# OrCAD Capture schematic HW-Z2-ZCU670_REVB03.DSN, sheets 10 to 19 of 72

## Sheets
10 010 Zynq Bank 503 - Config: size Custom
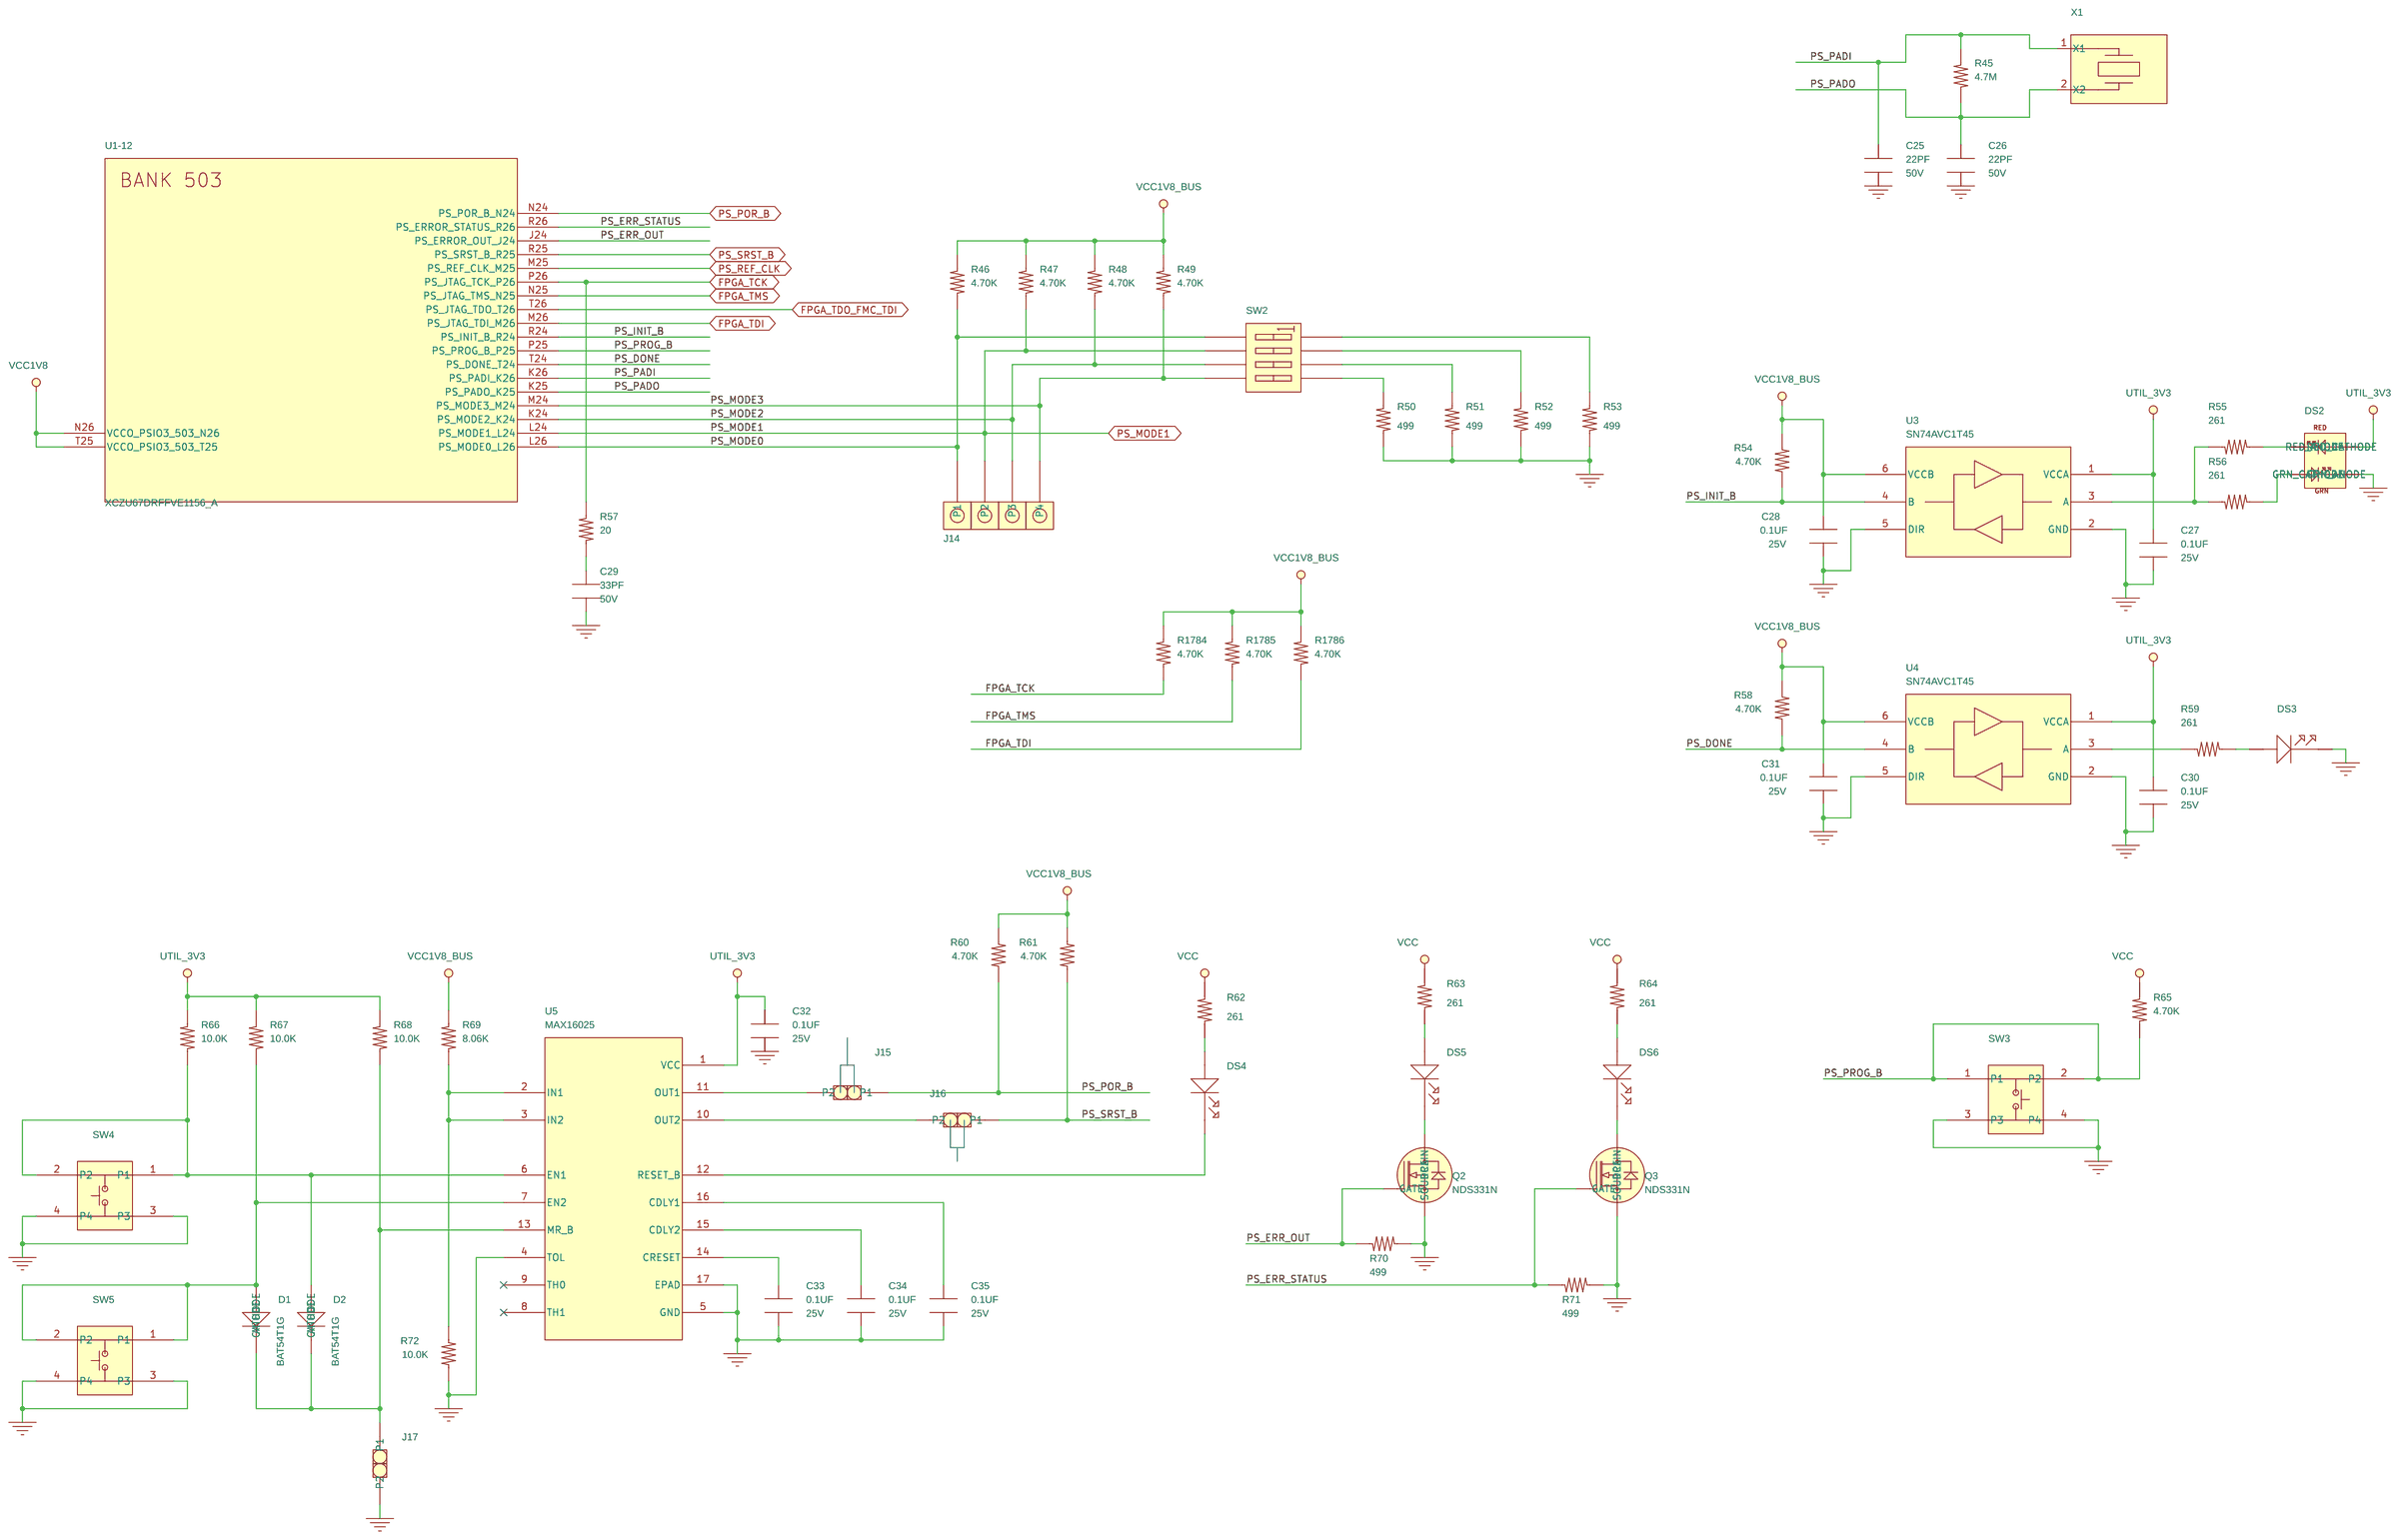
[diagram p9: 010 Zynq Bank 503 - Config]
11 011 Zynq Bank 504 - Memory: size Custom
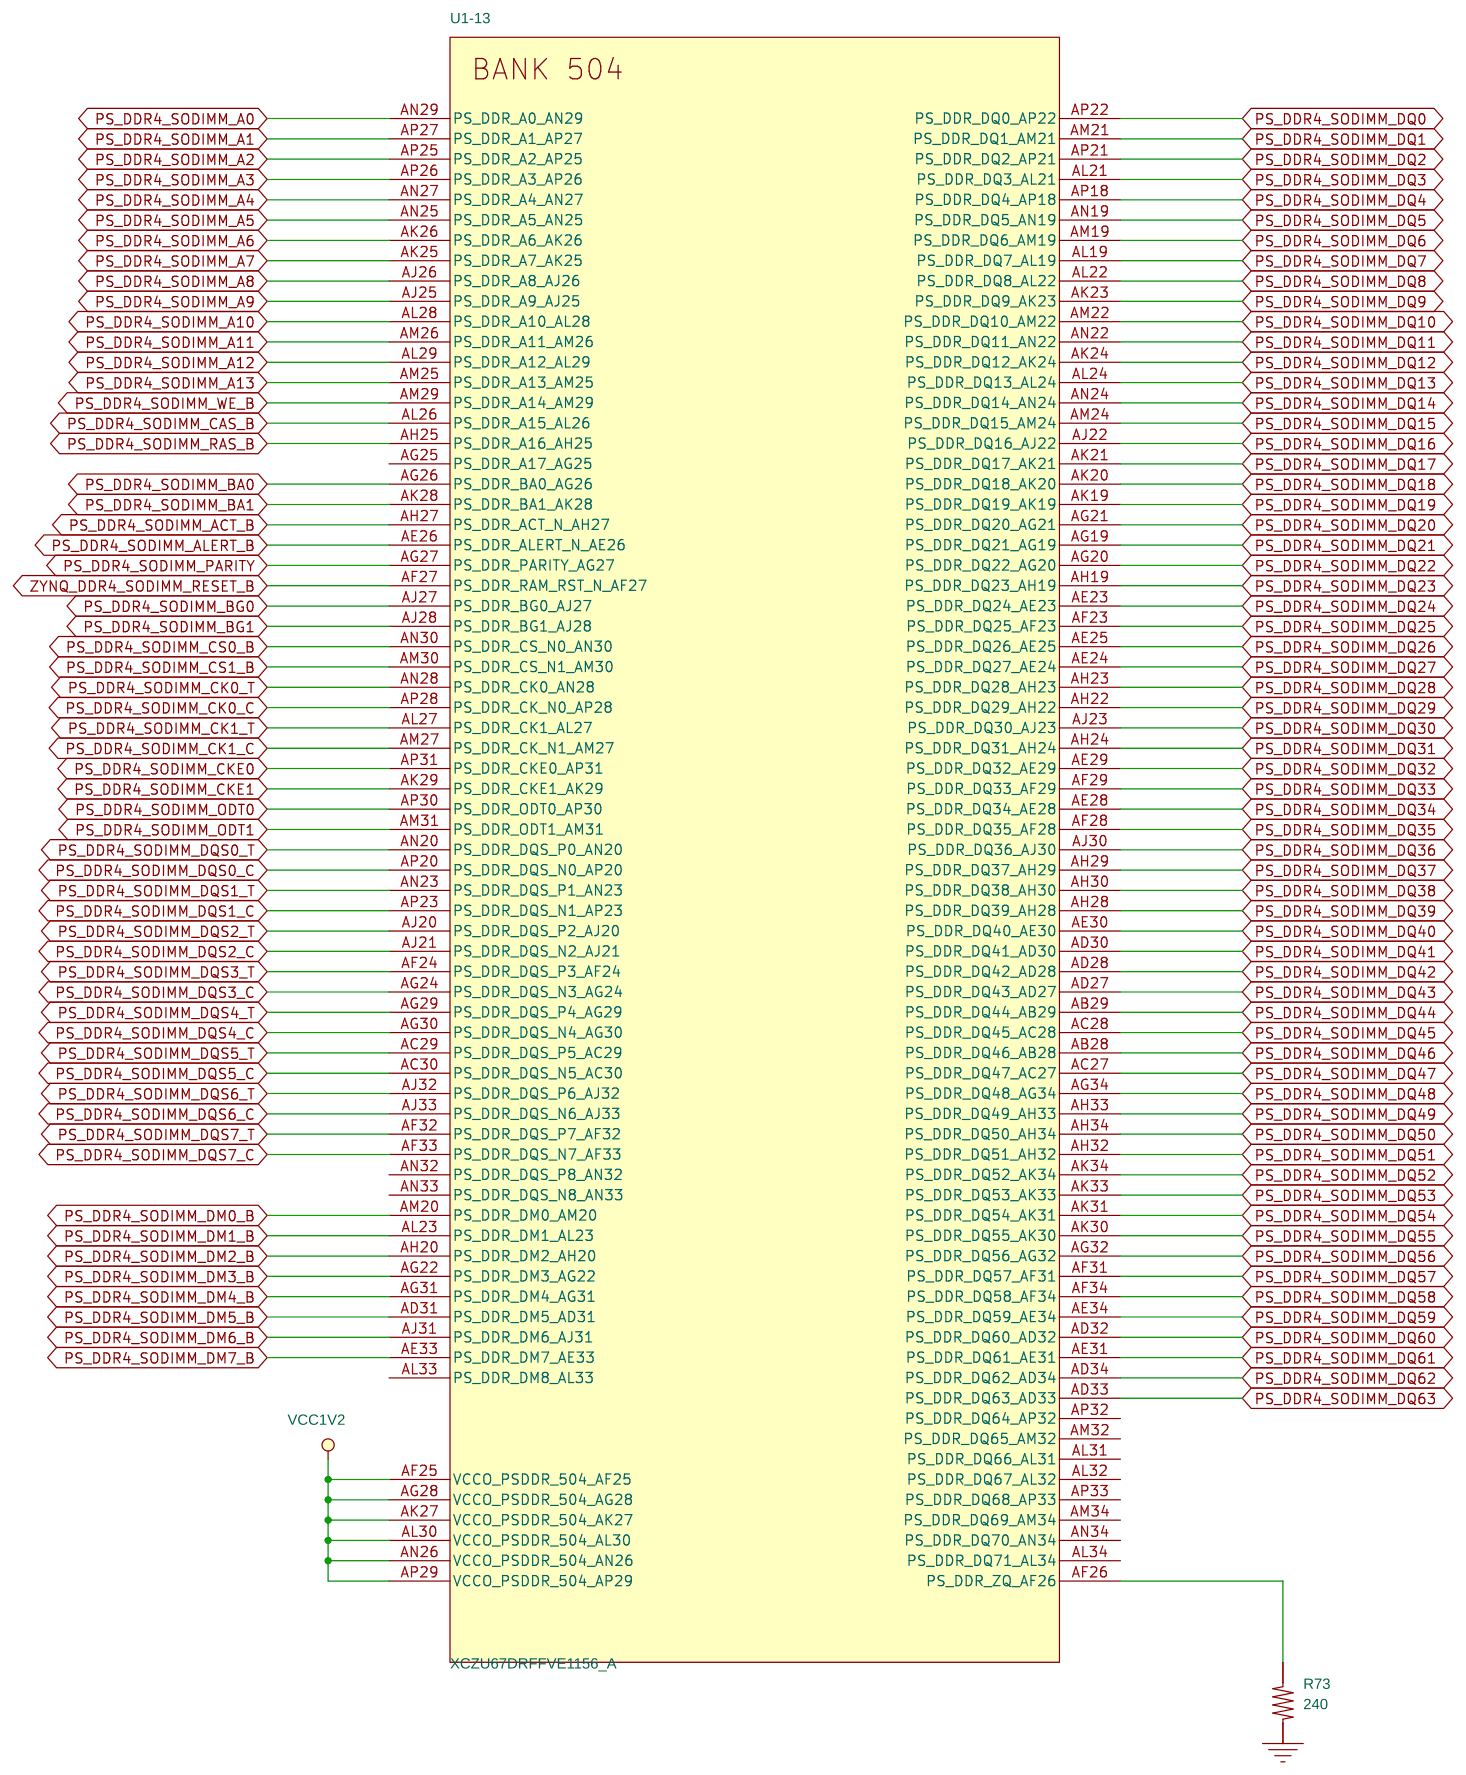
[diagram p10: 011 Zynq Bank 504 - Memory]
12 012 Zynq Bank 505 - GTR: size Custom
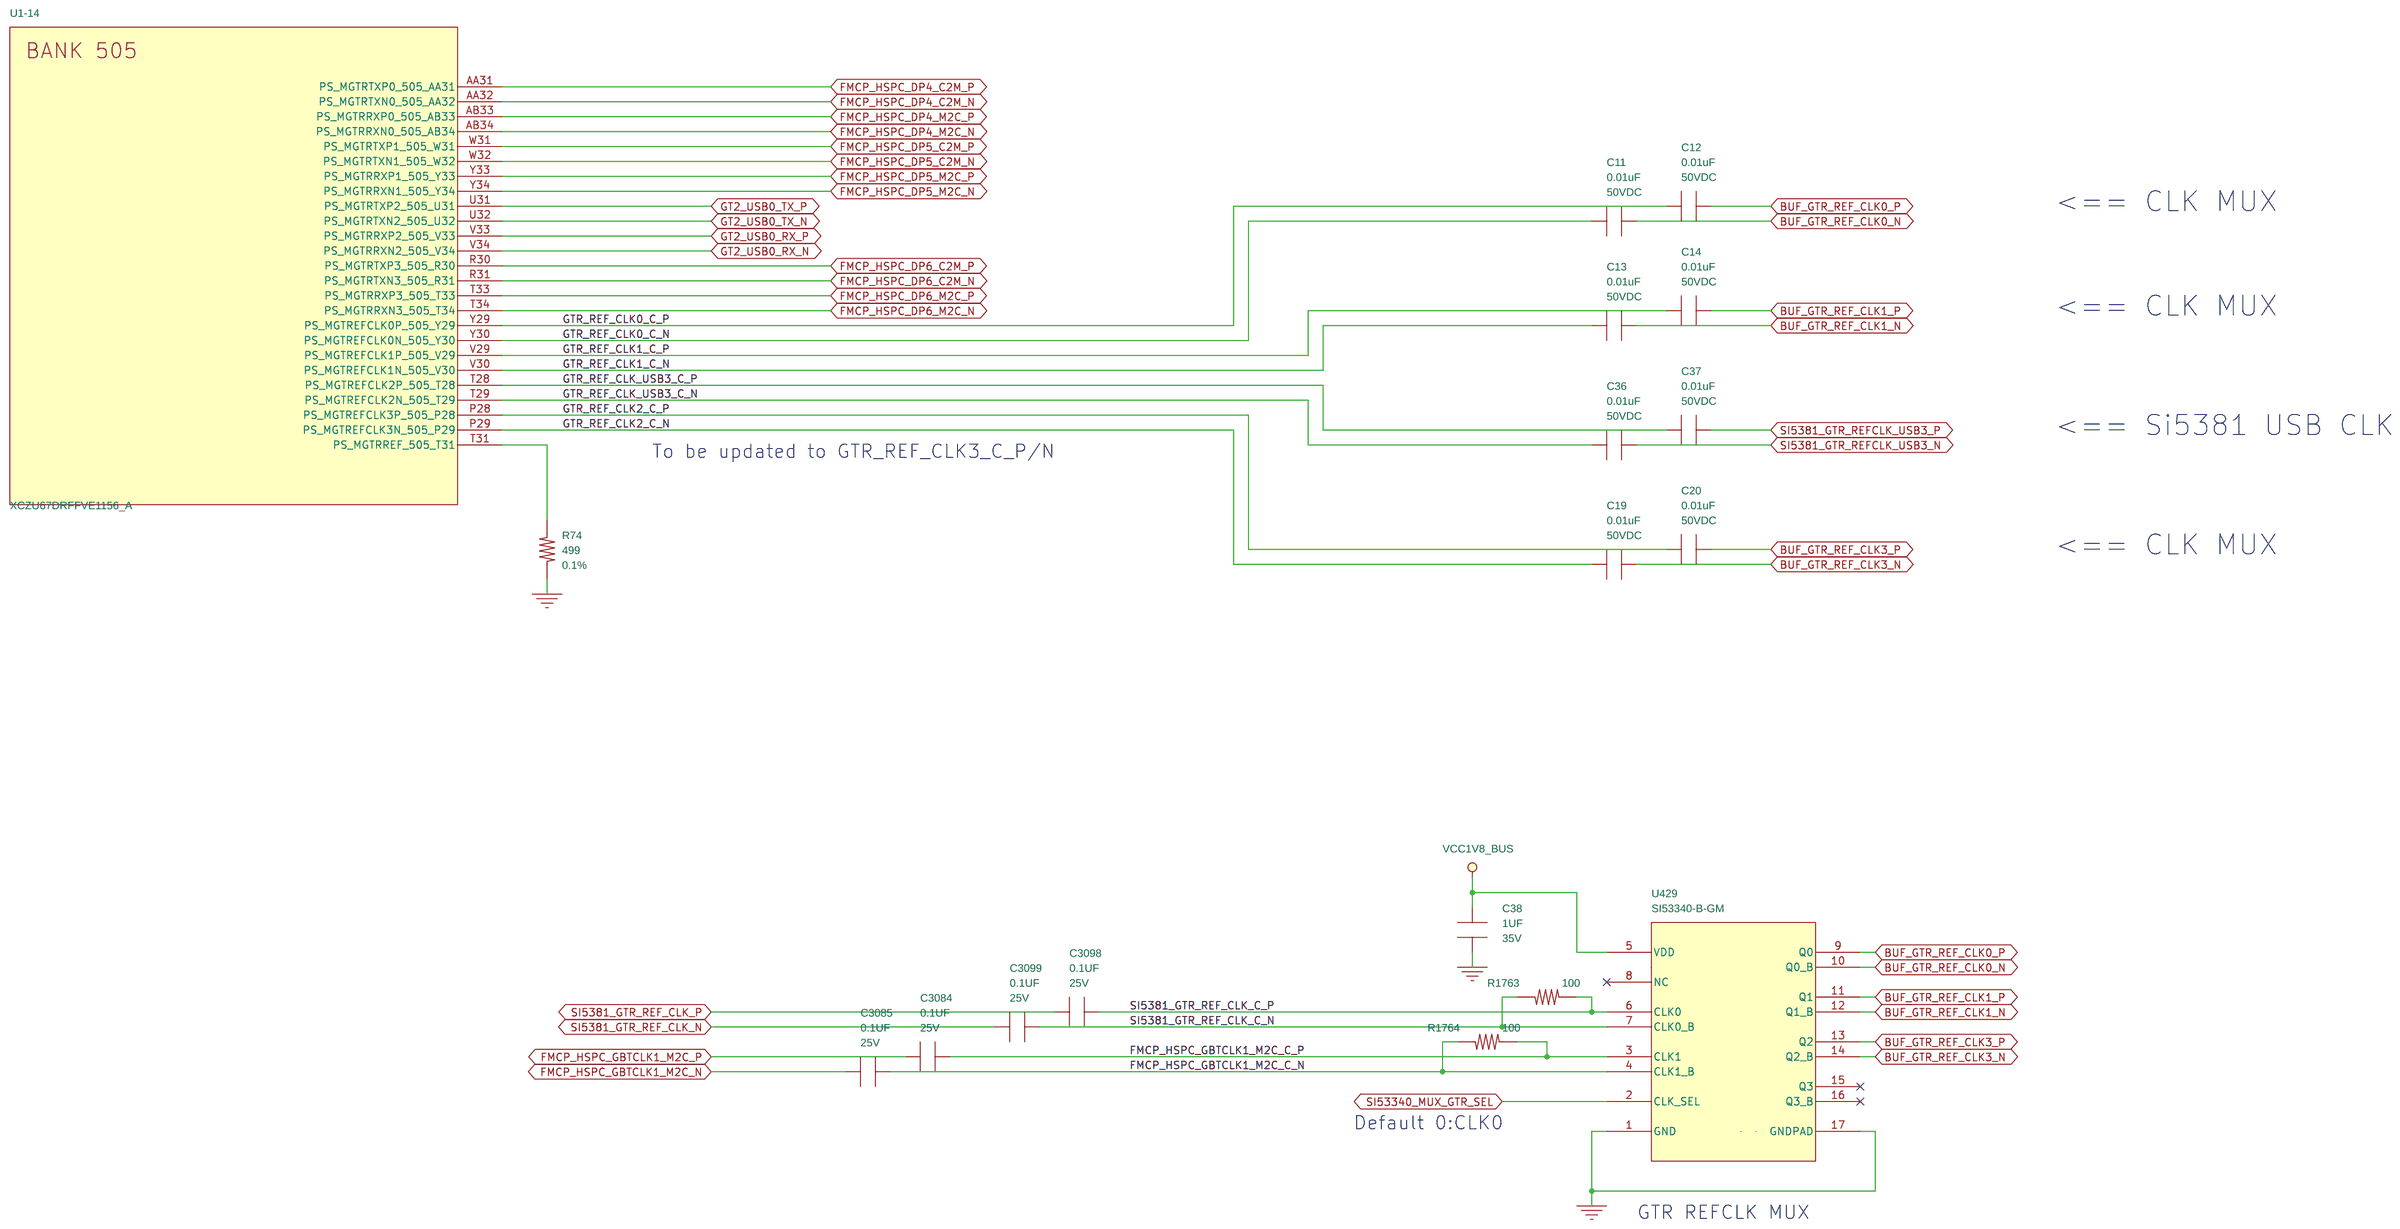
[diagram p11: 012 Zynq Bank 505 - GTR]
13 013 Zynq ADC Power: size Custom
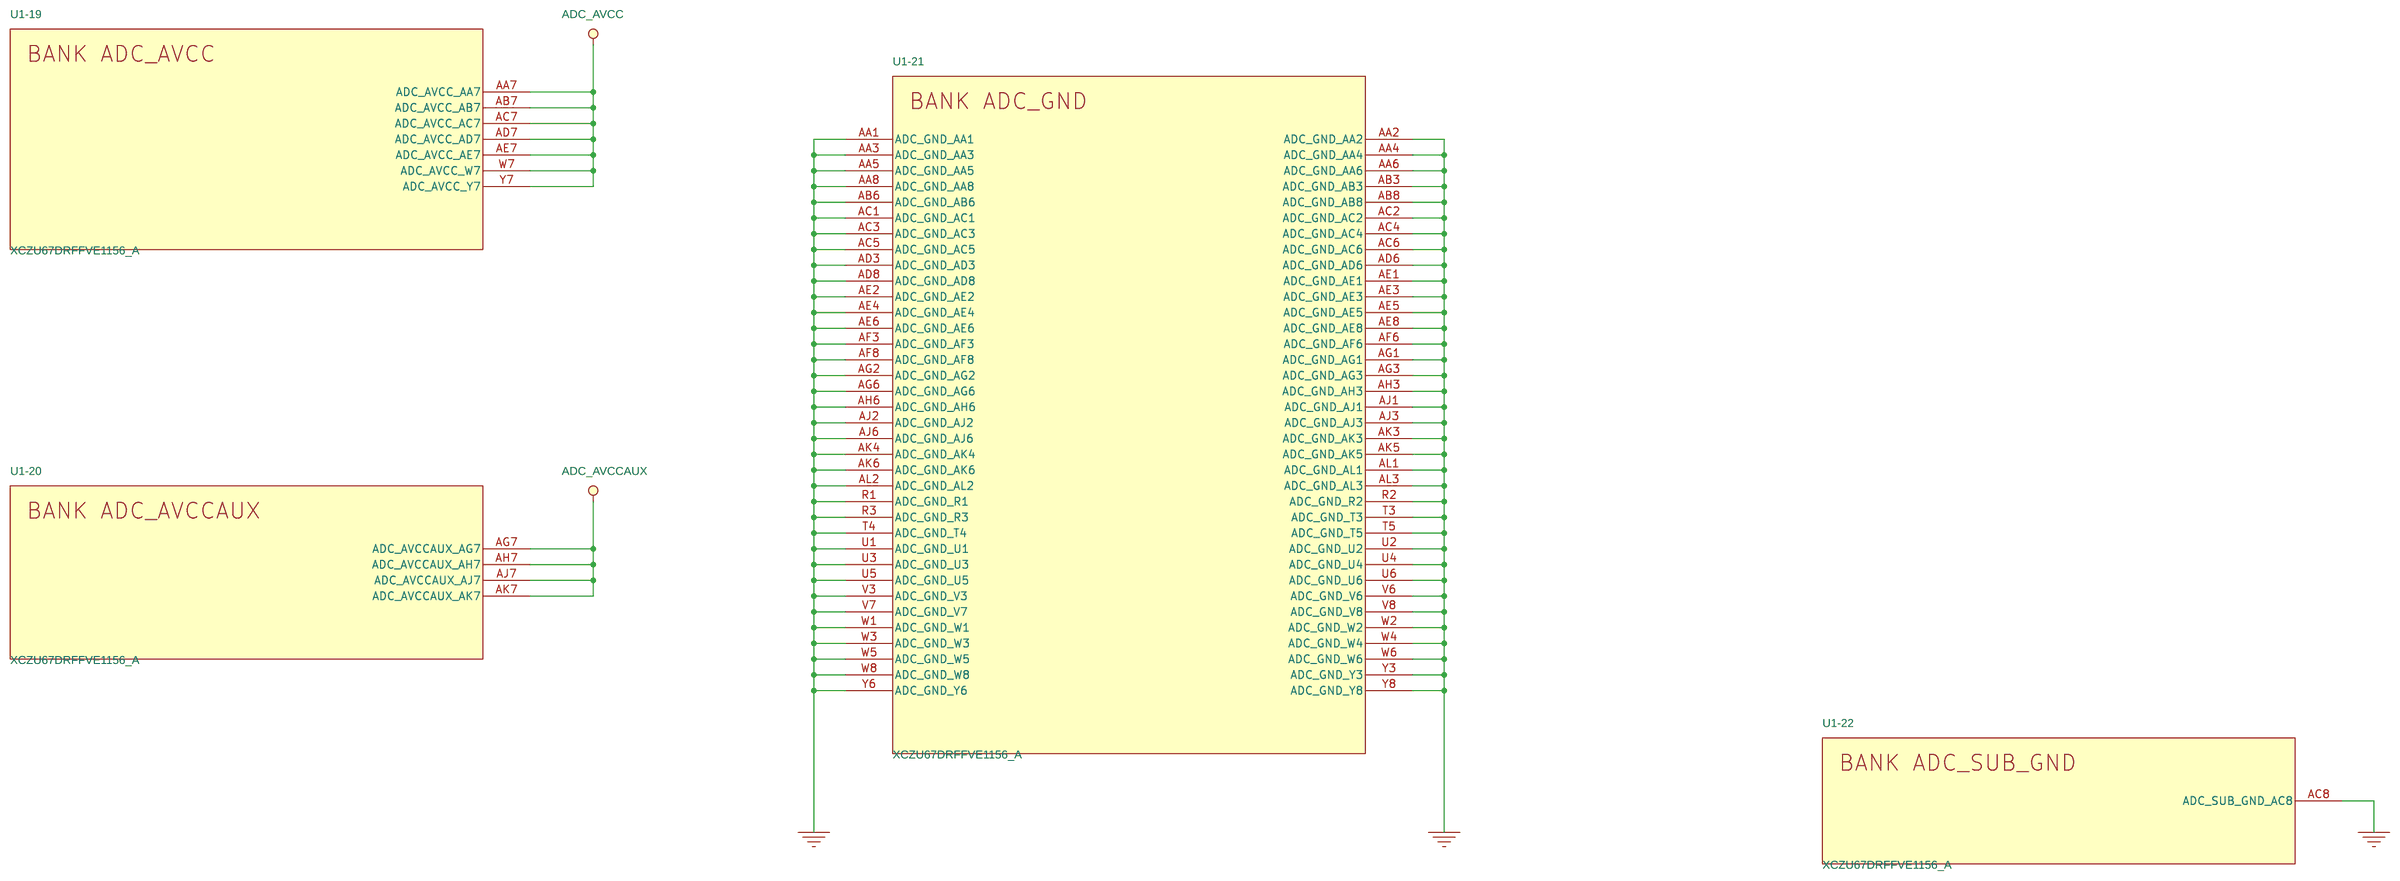
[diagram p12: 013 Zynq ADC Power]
14 014 Zynq DAC Power: size Custom
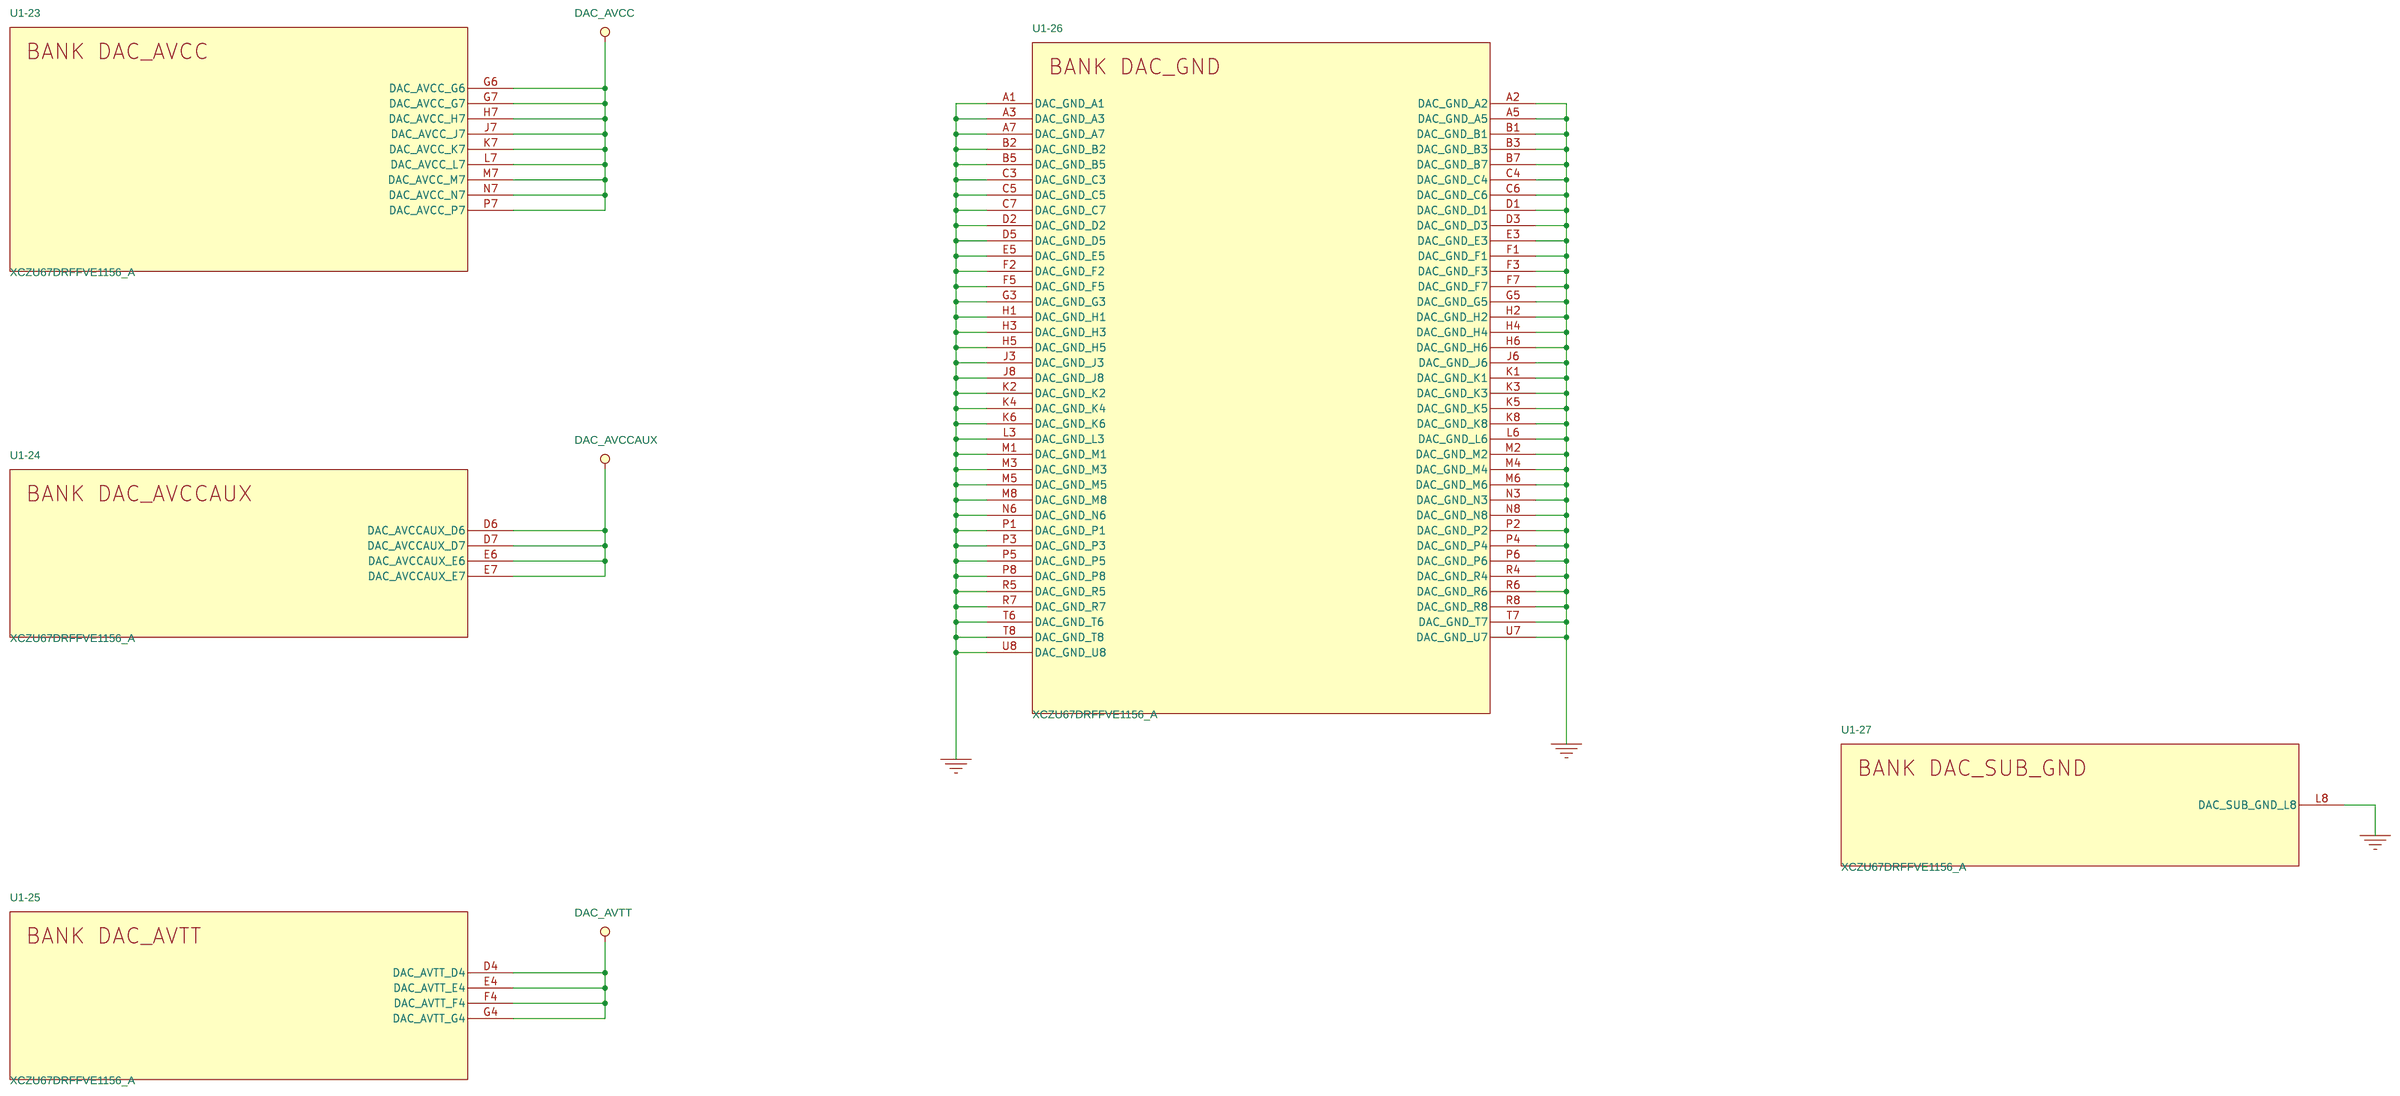
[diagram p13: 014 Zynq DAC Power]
15 015 Zynq Power 1: size Custom
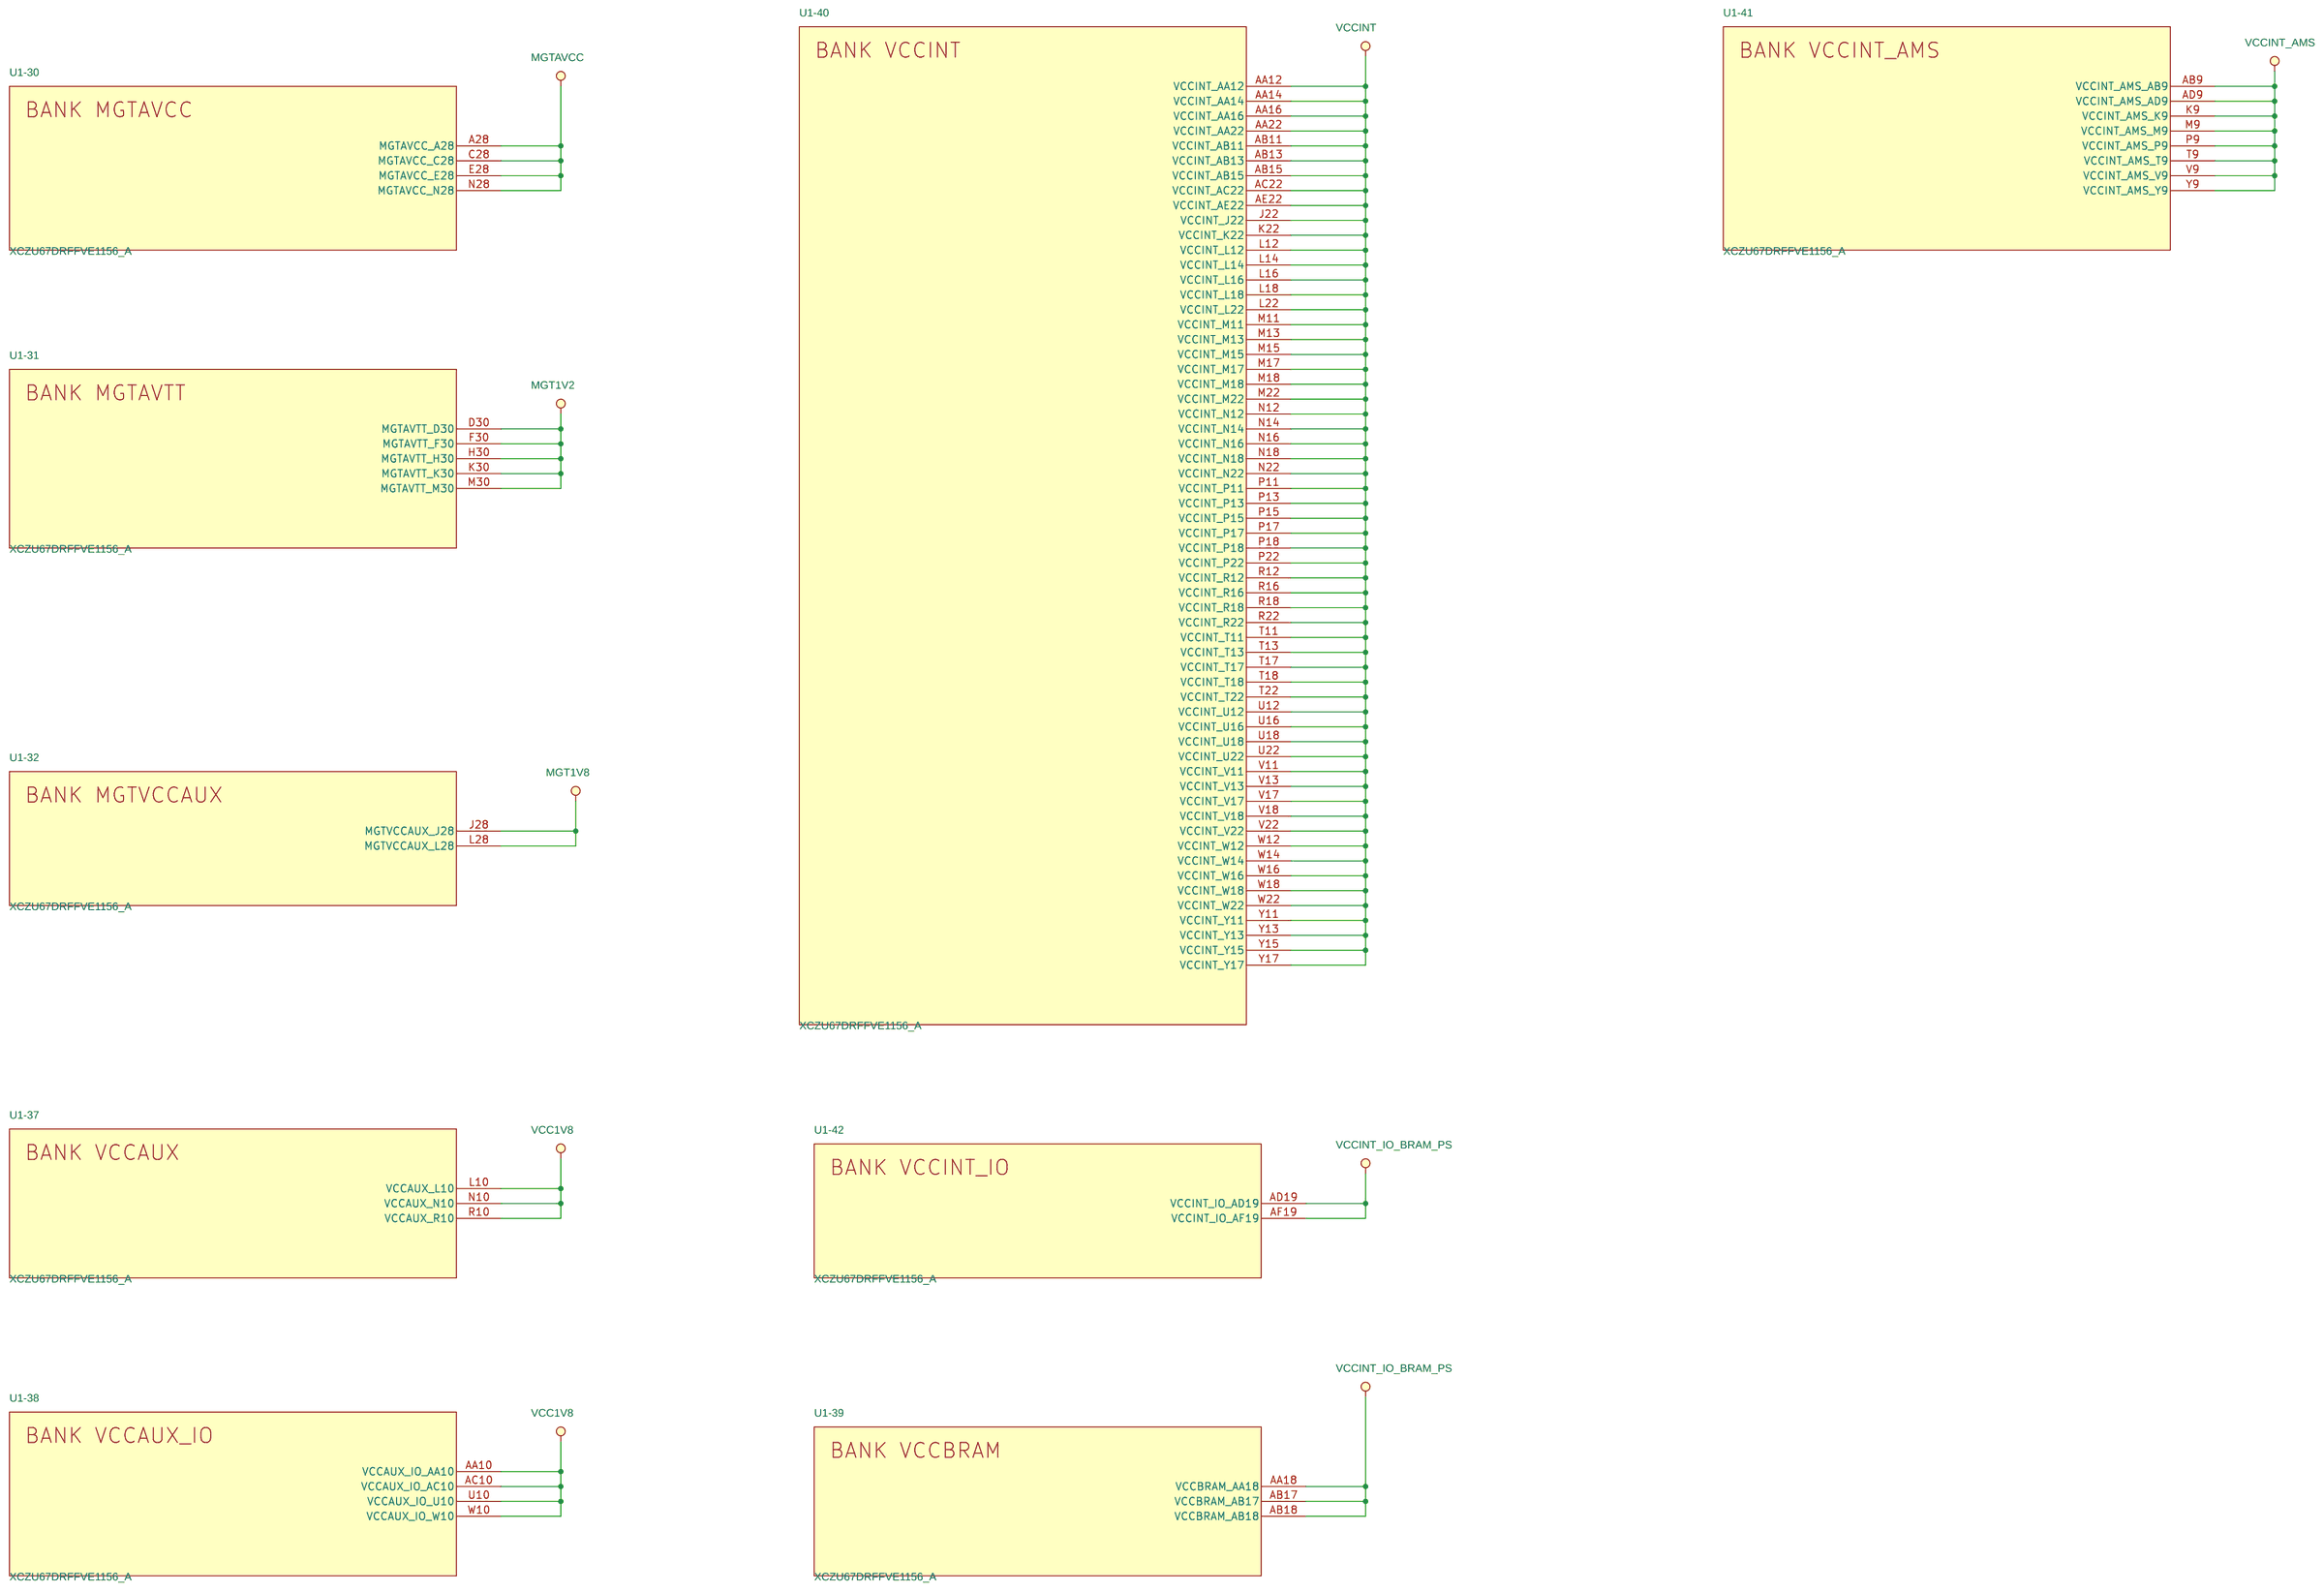
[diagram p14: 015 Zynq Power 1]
16 016 Zynq Power 2: size Custom
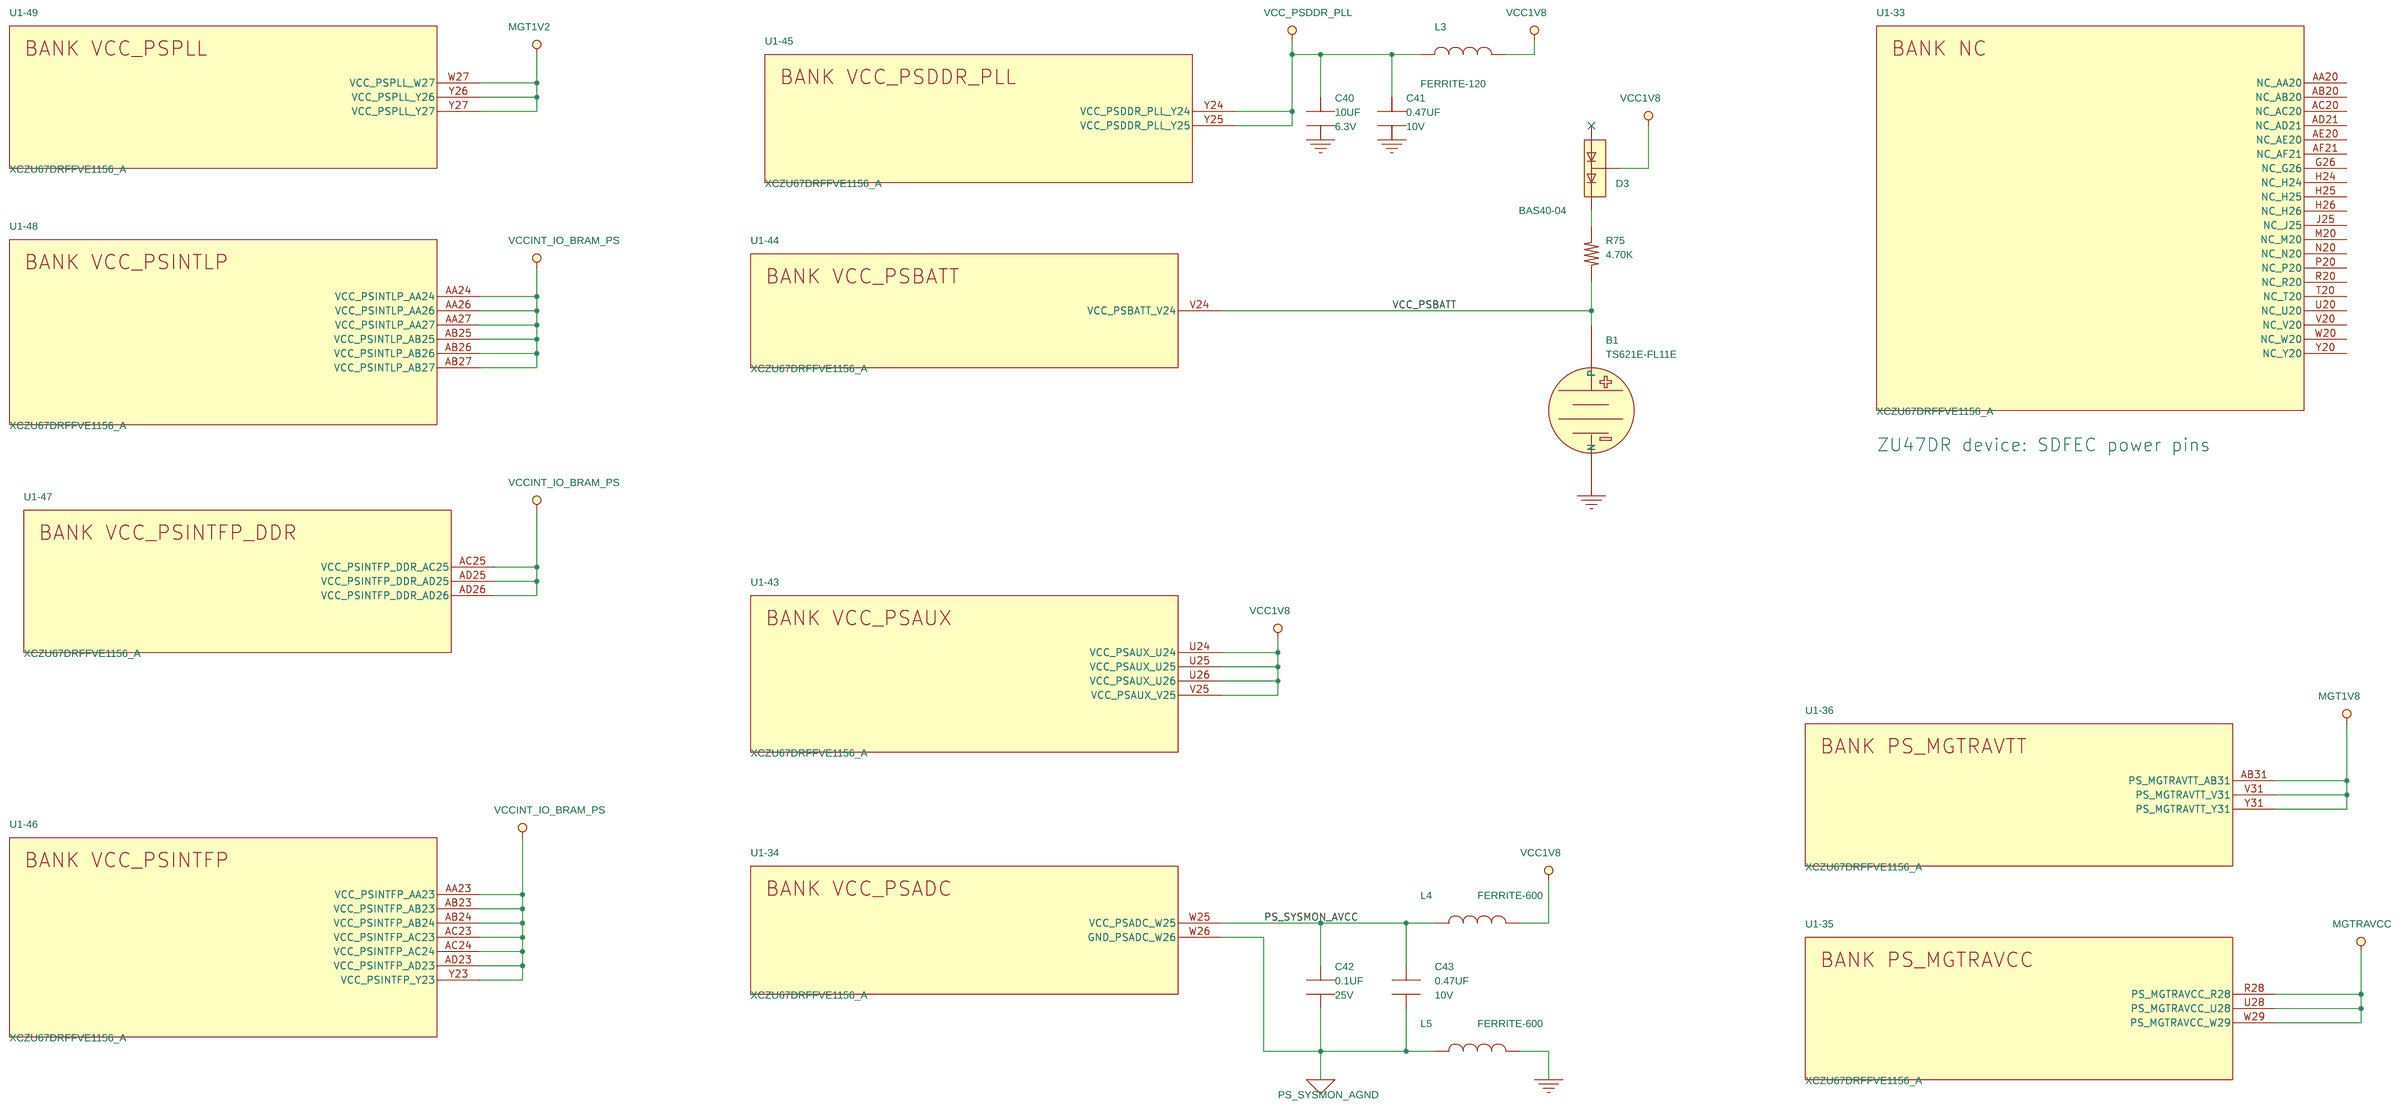
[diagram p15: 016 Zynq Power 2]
17 017 Zynq Decoupling: size Custom
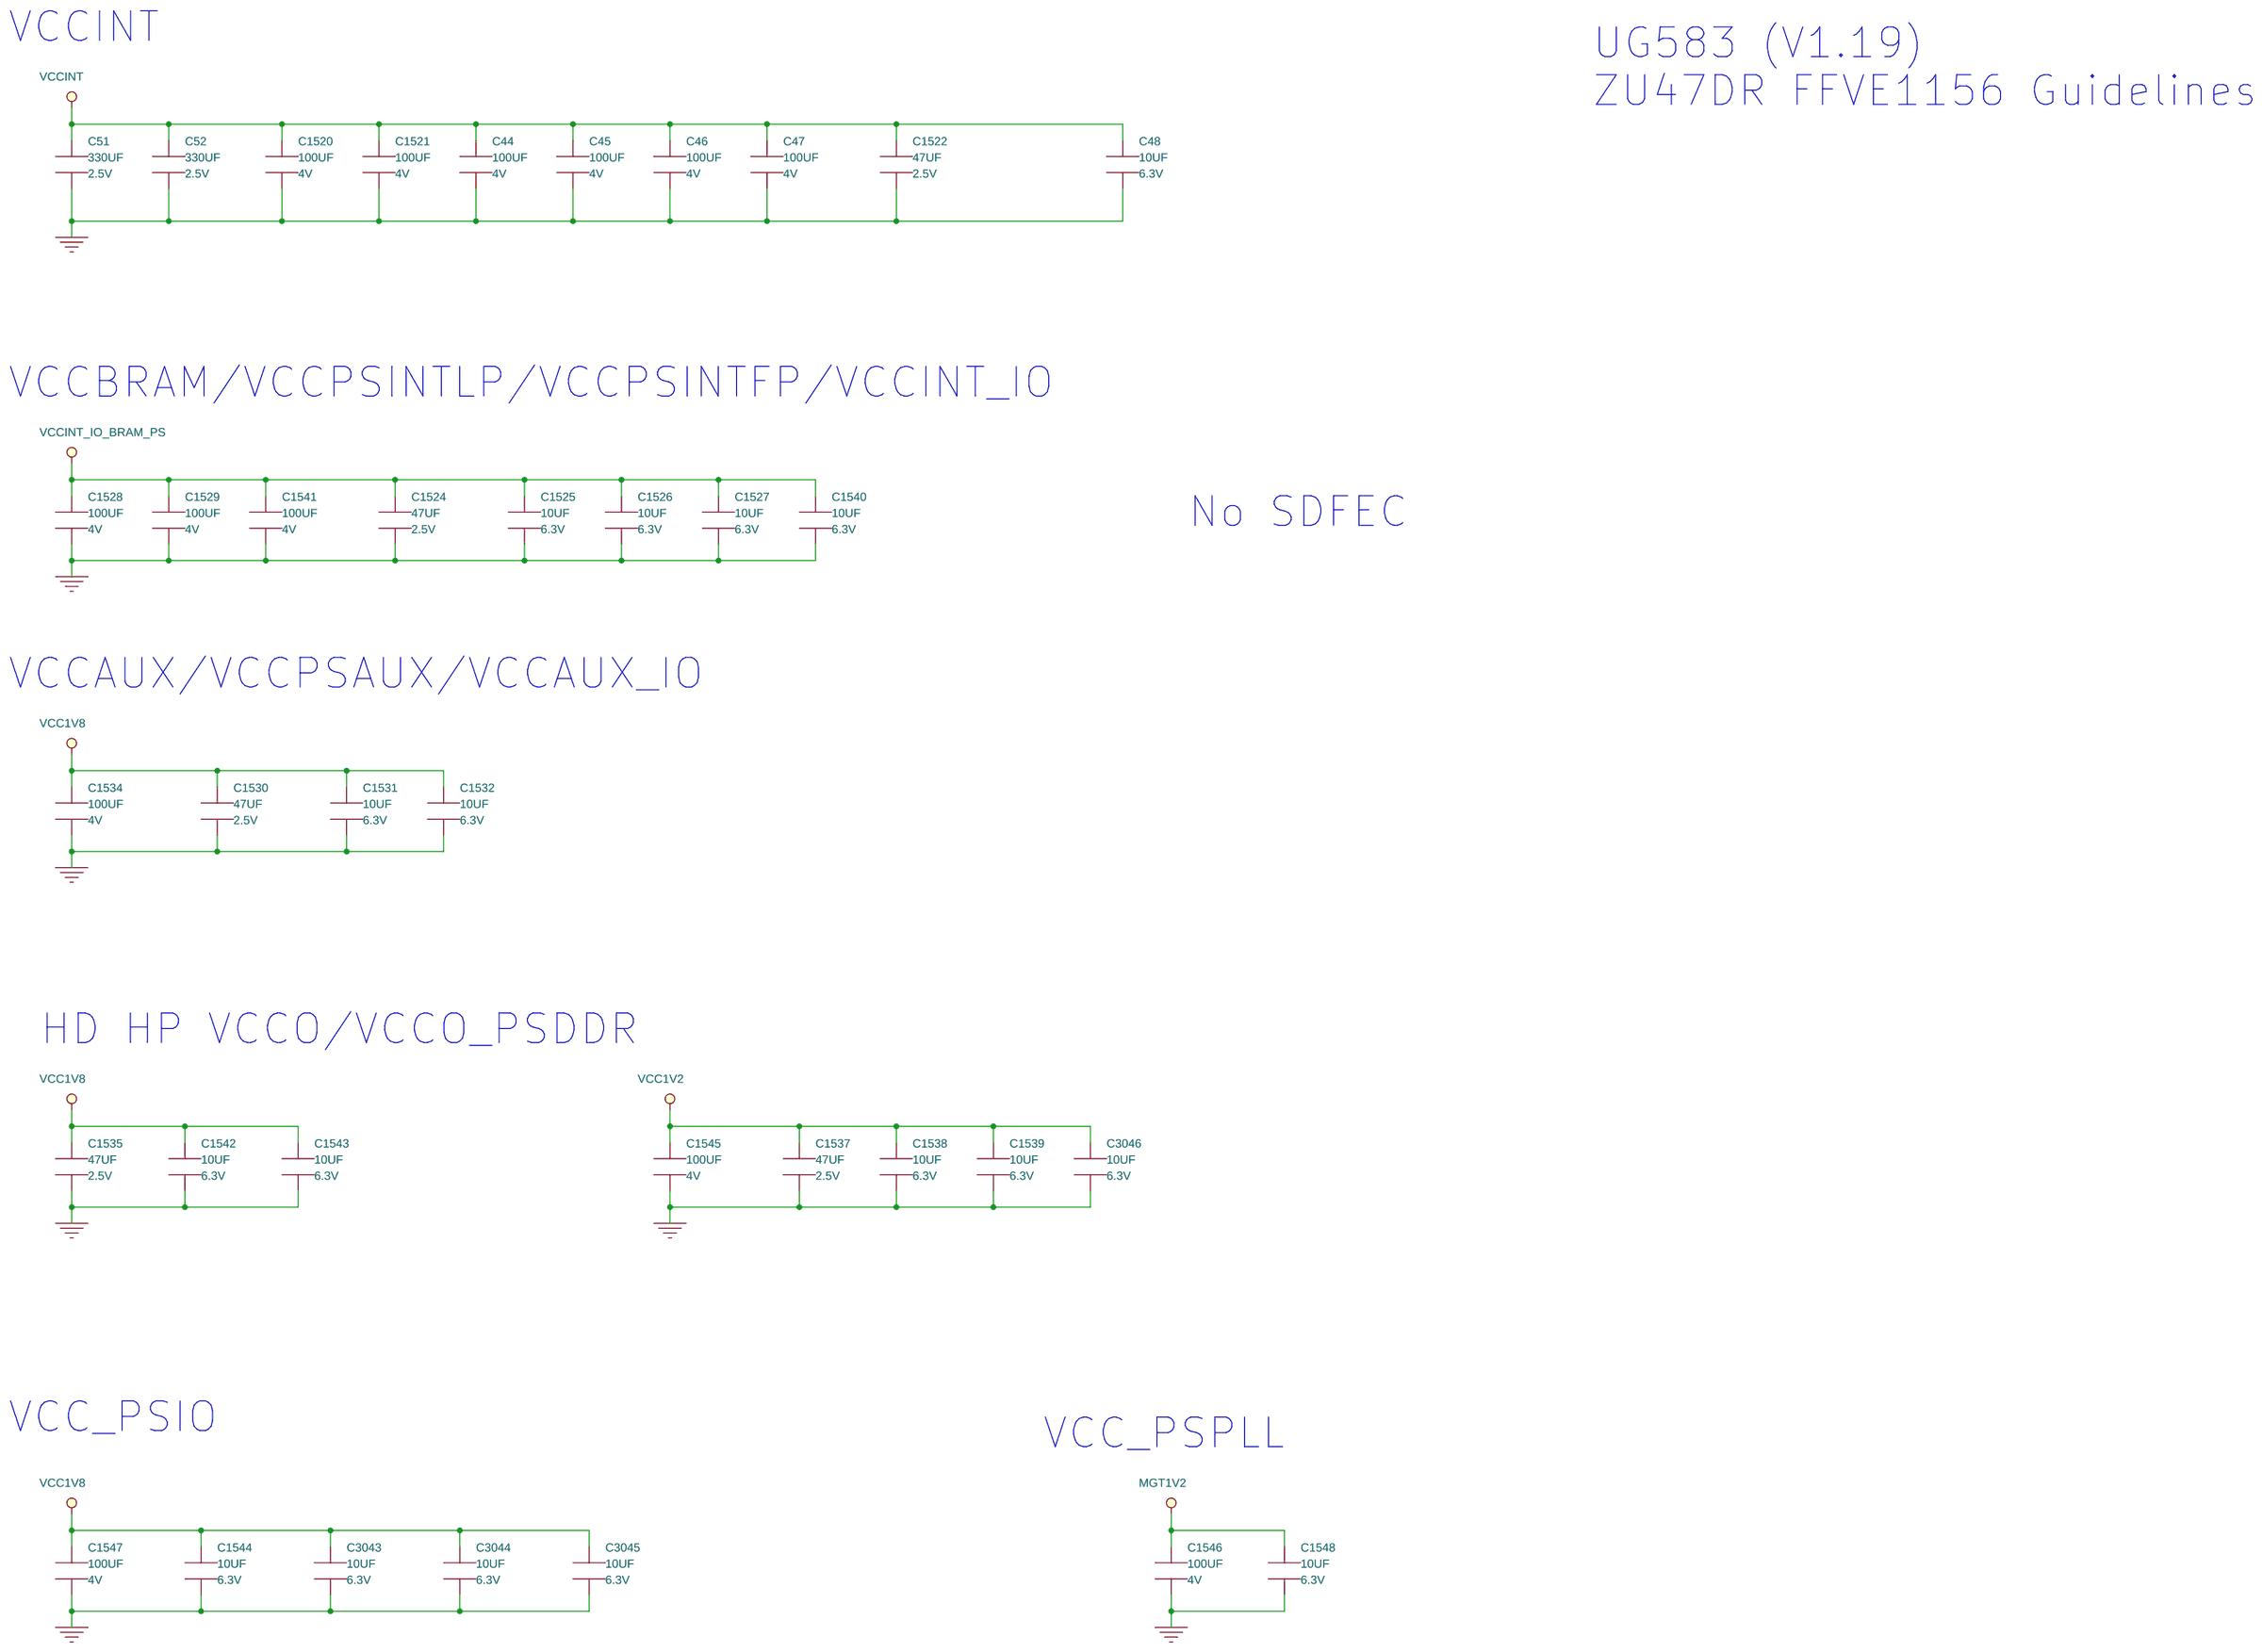
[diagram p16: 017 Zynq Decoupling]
18 018 Zynq Decoupling 2: size Custom
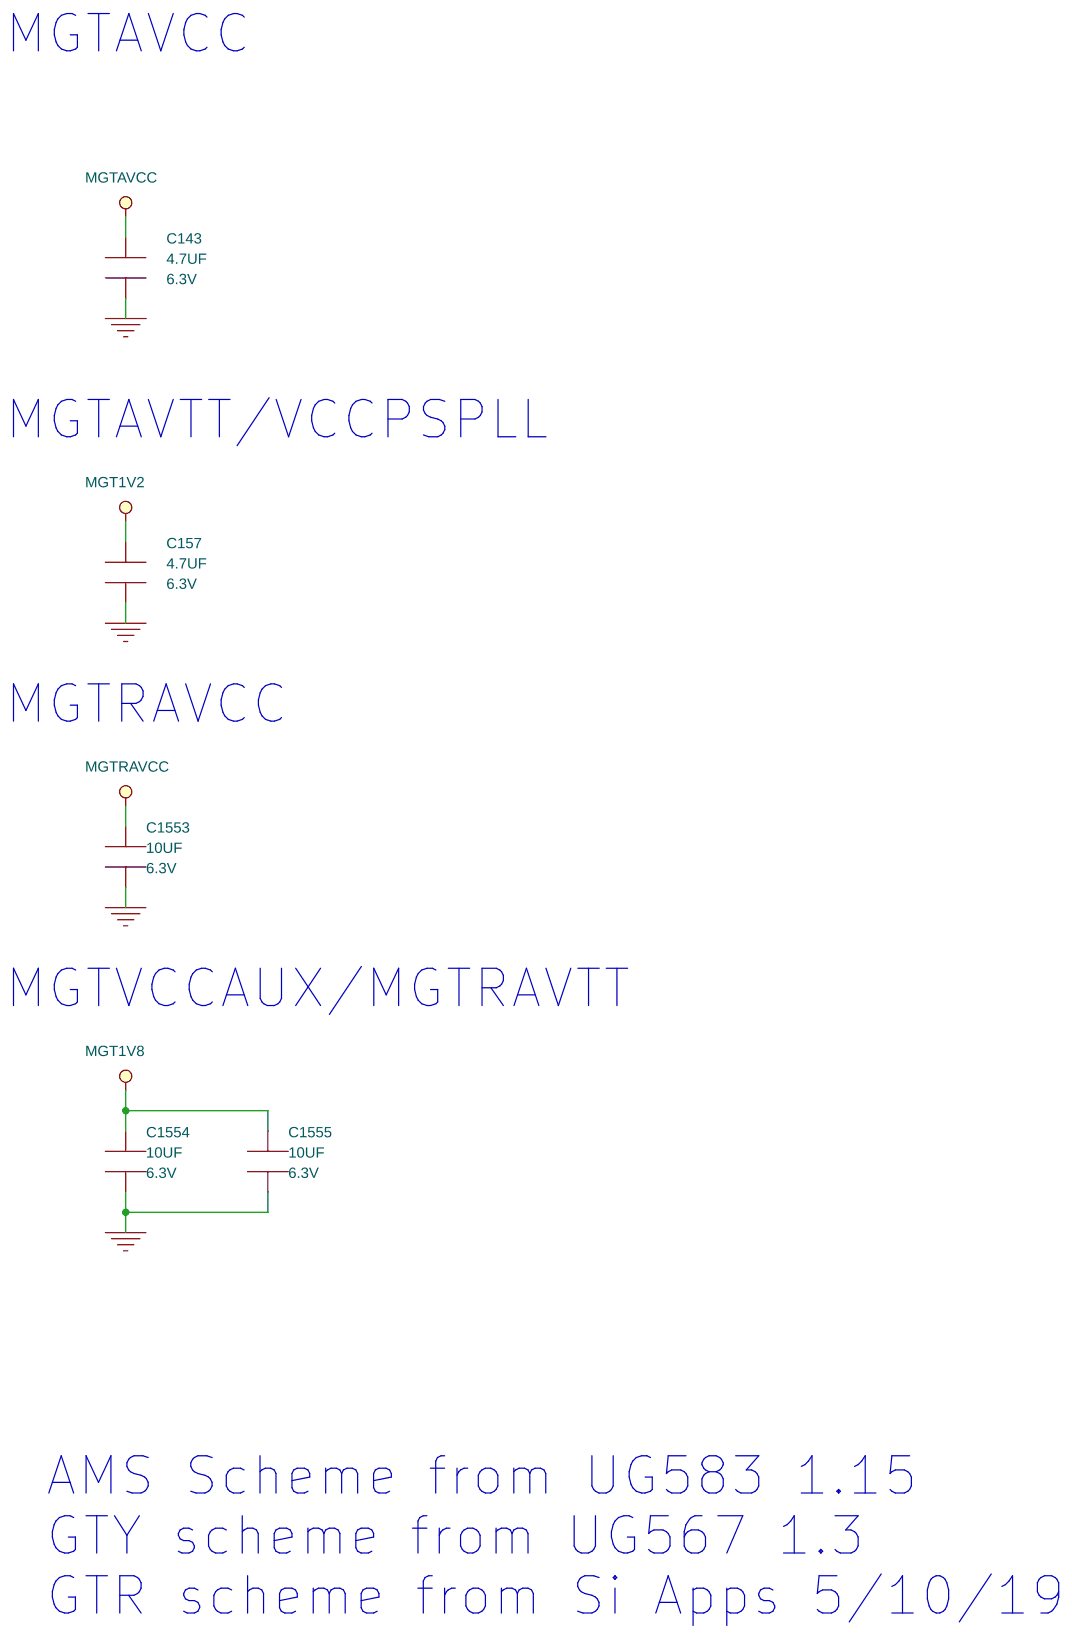
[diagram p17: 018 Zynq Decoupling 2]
19 019 Zynq GND: size Custom
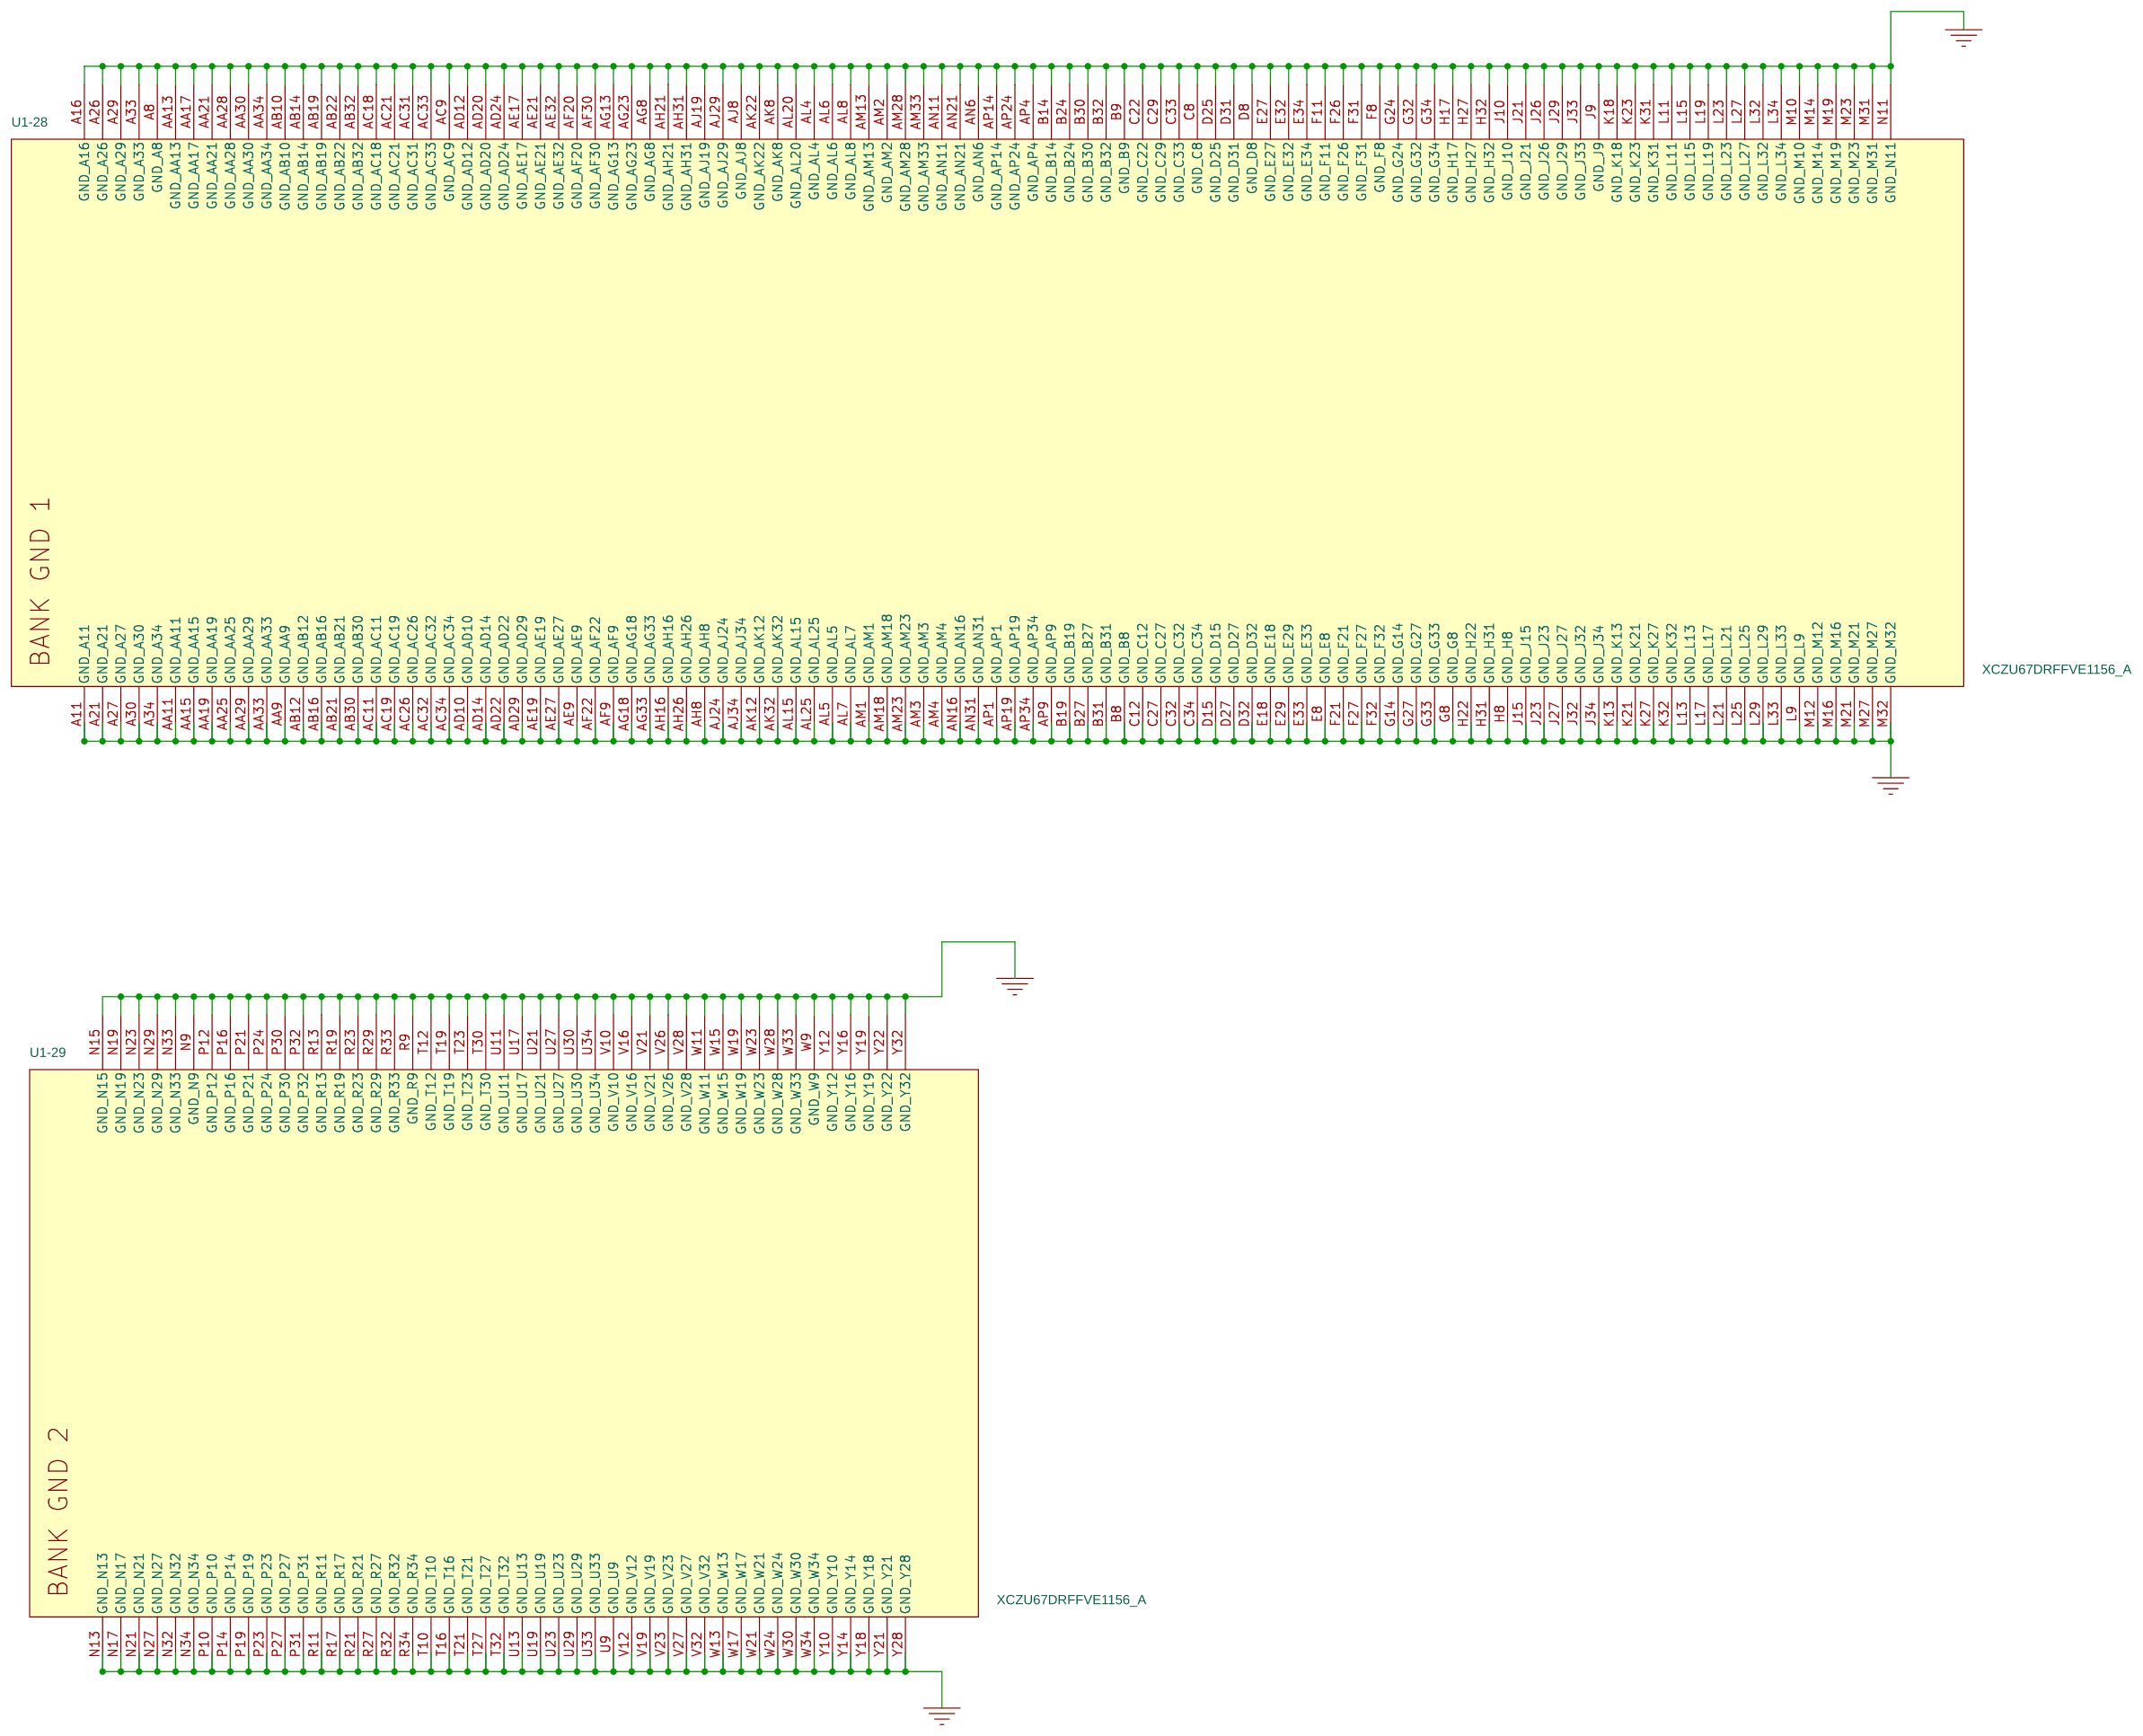
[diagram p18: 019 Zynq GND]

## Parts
sheet 010 Zynq Bank 503 - Config
C25  22PF  [CAPC100X50X56]
C26  22PF  [CAPC100X50X56]
C27  0.1UF  [CAPC100X50X55]
C28  0.1UF  [CAPC100X50X55]
C29  33PF  [CAPC100X50X56]
C30  0.1UF  [CAPC100X50X55]
C31  0.1UF  [CAPC100X50X55]
C32  0.1UF  [CAPC100X50X55]
C33  0.1UF  [CAPC100X50X55]
C34  0.1UF  [CAPC100X50X55]
C35  0.1UF  [CAPC100X50X55]
D1  BAT54T1G  [SOD_123]
D2  BAT54T1G  [SOD_123]
DS2  LED_GRN_RED  [HSMF_C15X]
DS3  LED-GRN-SMT  [LED_0603]
DS4  LED-RED-SMT  [LED_0603]
DS5  LED-RED-SMT  [LED_0603]
DS6  LED-RED-SMT  [LED_0603]
J14  HDR_1X4  [HDR_1X4]
J15  HDR_1X2  [HDR_1X2]
J16  HDR_1X2  [HDR_1X2]
J17  HDR_1X2  [HDR_1X2]
Q2  NDS331N  [SOT_23]
Q3  NDS331N  [SOT_23]
R45  4.7M  [RESC100X50X40]
R46  4.70K  [RESC100X50X40]
R47  4.70K  [RESC100X50X40]
R48  4.70K  [RESC100X50X40]
R49  4.70K  [RESC100X50X40]
R50  499  [RESC100X50X40]
R51  499  [RESC100X50X40]
R52  499  [RESC100X50X40]
R53  499  [RESC100X50X40]
R54  4.70K  [RESC100X50X40]
R55  261  [RESC100X50X40]
R56  261  [RESC100X50X40]
R57  20  [RESC100X50X40]
R58  4.70K  [RESC100X50X40]
R59  261  [RESC100X50X40]
R60  4.70K  [RESC100X50X40]
R61  4.70K  [RESC100X50X40]
R62  261  [RESC100X50X40]
R63  261  [RESC100X50X40]
R64  261  [RESC100X50X40]
R65  4.70K  [RESC100X50X40]
R66  10.0K  [RESC100X50X40]
R67  10.0K  [RESC100X50X40]
R68  10.0K  [RESC100X50X40]
R69  8.06K  [RESC100X50X40]
R70  499  [RESC100X50X40]
R71  499  [RESC100X50X40]
R72  10.0K  [RESC100X50X40]
R1784  4.70K  [RESC100X50X40]
R1785  4.70K  [RESC100X50X40]
R1786  4.70K  [RESC100X50X40]
SW2  SDA04H1SBD  [SW_SDA_8P]
SW3  TL3301EF100QG  [SW_TL3301_G_4P]
SW4  TL3301EF100QG  [SW_TL3301_G_4P]
SW5  TL3301EF100QG  [SW_TL3301_G_4P]
U3  SN74AVC1T45  [SC70_6]
U4  SN74AVC1T45  [SC70_6]
U5  MAX16025  [TQFN_16]
X1  32.768KHZ  [XTAL_TXC_9HT10]
sheet 011 Zynq Bank 504 - Memory
R73  240  [RESC100X50X40]
sheet 012 Zynq Bank 505 - GTR
C11  0.01uF  [CAPC100X50X55]
C12  0.01uF  [CAPC100X50X55]
C13  0.01uF  [CAPC100X50X55]
C14  0.01uF  [CAPC100X50X55]
C19  0.01uF  [CAPC100X50X55]
C20  0.01uF  [CAPC100X50X55]
C36  0.01uF  [CAPC100X50X55]
C37  0.01uF  [CAPC100X50X55]
C38  1UF  [CAPC100X50X60]
C3084  0.1UF  [CAPC60X30X40]
C3085  0.1UF  [CAPC60X30X40]
C3098  0.1UF  [CAPC60X30X40]
C3099  0.1UF  [CAPC60X30X40]
R74  499  [RESC100X50X40]
R1763  100  [RESC60X30X26]
R1764  100  [RESC60X30X26]
U429  SI53340-B-GM  [QFN16_SI_3X3MM]
sheet 016 Zynq Power 2
B1  TS621E-FL11E  [BAT_TS518_TS621_DUAL]
C40  10UF  [CAPC100X50X70]
C41  0.47UF  [CAPC100X50X55]
C42  0.1UF  [CAPC100X50X55]
C43  0.47UF  [CAPC100X50X55]
D3  BAS40-04  [SOT_23]
L3  FERRITE-120  [INDC160X80X65]
L4  FERRITE-600  [INDC200X125X110]
L5  FERRITE-600  [INDC200X125X110]
R75  4.70K  [RESC100X50X40]
U1  XCZU67DRFFVE1156_A  [SOC_1156_1MM_IRON_XILINX]  (sections -1,-10,-11,-12,-13,-14,-15,-16,-17,-18,-19,-2,-20,-21,-22,-23,-24,-25,-26,-27,-28,-29,-3,-30,-31,-32,-33,-34,-35,-36,-37,-38,-39,-4,-40,-41,-42,-43,-44,-45,-46,-47,-48,-49,-5,-6,-7,-8,-9)
sheet 017 Zynq Decoupling
C44  100UF  [CAPC200X125X145]
C45  100UF  [CAPC200X125X145]
C46  100UF  [CAPC200X125X145]
C47  100UF  [CAPC200X125X145]
C48  10UF  [CAPC100X50X70]
C51  330UF  [CAPC320X250X280]
C52  330UF  [CAPC320X250X280]
C1520  100UF  [CAPC200X125X145]
C1521  100UF  [CAPC200X125X145]
C1522  47UF  [CAPC160X80X80]
C1524  47UF  [CAPC160X80X80]
C1525  10UF  [CAPC100X50X70]
C1526  10UF  [CAPC100X50X70]
C1527  10UF  [CAPC100X50X70]
C1528  100UF  [CAPC200X125X145]
C1529  100UF  [CAPC200X125X145]
C1530  47UF  [CAPC160X80X80]
C1531  10UF  [CAPC100X50X70]
C1532  10UF  [CAPC100X50X70]
C1534  100UF  [CAPC200X125X145]
C1535  47UF  [CAPC160X80X80]
C1537  47UF  [CAPC160X80X80]
C1538  10UF  [CAPC100X50X70]
C1539  10UF  [CAPC100X50X70]
C1540  10UF  [CAPC100X50X70]
C1541  100UF  [CAPC200X125X145]
C1542  10UF  [CAPC100X50X70]
C1543  10UF  [CAPC100X50X70]
C1544  10UF  [CAPC100X50X70]
C1545  100UF  [CAPC200X125X145]
C1546  100UF  [CAPC200X125X145]
C1547  100UF  [CAPC200X125X145]
C1548  10UF  [CAPC100X50X70]
C3043  10UF  [CAPC100X50X70]
C3044  10UF  [CAPC100X50X70]
C3045  10UF  [CAPC100X50X70]
C3046  10UF  [CAPC100X50X70]
sheet 018 Zynq Decoupling 2
C143  4.7UF  [CAPC100X50X60]
C157  4.7UF  [CAPC100X50X60]
C1553  10UF  [CAPC100X50X70]
C1554  10UF  [CAPC100X50X70]
C1555  10UF  [CAPC100X50X70]

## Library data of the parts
C25 C26 = CAP_NP: Cap Cer 22pF 5% 50V C0G 0402; ALT_SYMBOLS: CAPC100X50X55RND; Agile Part Number: CAP-00003-01; CIP Link: http://xsjbrdwin1/CIP-E/Component/Index/All?pn=100099; Dielectric Type: C0G,NP0; OWNER: 3709; PRICE: 0; Part Type: CERAMIC; PartType: CERAMIC; ROHS: Yes; Tolerance: 5%; Voltage: 50V; barcode: 100099
C27 C28 C30-C35 C42 = CAP_NP: Cap Cer 100nF 10% 25V X5R 0402; ALT_SYMBOLS: CAPC100X50X55RND; Agile Part Number: CAP-00068-01; CIP Link: http://xsjbrdwin1/CIP-E/Component/Index/All?pn=100040; Dielectric Type: X5R; OWNER: 4001; PRICE: 0.01; Part Type: CERAMIC; PartType: CERAMIC; ROHS: Yes; Tolerance: 10%; Voltage: 25V; barcode: 100040
C29 = CAP_NP: Cap Cer 33pF 5% 50V C0G 0402; ALT_SYMBOLS: CAPC100X50X56RND; Agile Part Number: CAP-00013-01; CIP Link: http://xsjbrdwin1/CIP-E/Component/Index/All?pn=100188; Dielectric Type: NP0; OWNER: 3670; PRICE: 0; Part Type: CERAMIC; PartType: CERAMIC; ROHS: Yes; Tolerance: 5%; Voltage: 50V; barcode: 100188
D1 D2 = BAT54T1G: Diode Schottky 200mA 30V SOD-123; Agile Part Number: DIO-00008-01; Barcode: 300002; CIP Link: http://xsjbrdwin1/CIP-E/Component/Index/All?pn=300002; OWNER: 3501; PRICE: 0.08; Part Type: SWITCHING; PartType: SWITCHING; Power: 400MW; ROHS: 1; Rated Power: 400MW; Voltage: 30V
DS2 = HSMF_C155: LED Bi-Color Clear Green/Red 20mA 5V 570/635nm Dom 3.2x2.7mm SMT; Agile Part Number: DIO-00103-01; Barcode: 70000027; CIP Link: http://xsjbrdwin1/CIP-E/Component/Index/All?pn=70000027; Part Type: LED DUAL
DS3 = LED: LED Green Diffused 20mA 5V 570nm 0603; Agile Part Number: DIO-00003-01; Barcode: 300021; CIP Link: http://xsjbrdwin1/CIP-E/Component/Index/All?pn=300021; OWNER: 4001; PRICE: 0.1; Power: 2.2-20MA; ROHS: Yes; Rated Power: 2.2-20MA; Voltage: 2.2V
DS4-DS6 = LED: LED Red Diffused 20mA 5V 630nm 0603; Agile Part Number: DIO-00005-01; Barcode: 300022; CIP Link: http://xsjbrdwin1/CIP-E/Component/Index/All?pn=300022; OWNER: 4001; PRICE: 0.08; Power: 2.0-20MA; ROHS: Yes; Rated Power: 2.0-20MA; Voltage: 2.0V
J14 = HDR_1X4: Conn Hdr Vert 4  Pos 1x4 2.54mm P Black TH; Agile Part Number: CON-00039-01; Barcode: 390104; CIP Link: http://xsjbrdwin1/CIP-E/Component/Index/All?pn=390104; Part Type: HEADER; Pins: 4PINS; Pitch: 0.100; ROHS: Yes
J15-J17 = HDR_1X2: Conn Hdr Male Vert 2 Pos 1x2 2.54mm P Black TH; Agile Part Number: CON-00037-01; Barcode: 390102; CIP Link: http://xsjbrdwin1/CIP-E/Component/Index/All?pn=390102; OWNER: 4001; PRICE: 0.03; Part Type: HEADER; PartType: HEADER; Pins: 2PINS; Pitch: 0.100; ROHS: Yes
Q2 Q3 = FET-3PIN: MOSFET N-Ch 20V 1.3A 160mR SSOT-3; Agile Part Number: TRN-00012-01; Barcode: 500100; CIP Link: http://xsjbrdwin1/CIP-E/Component/Index/All?pn=500100; OWNER: 4001; PRICE: 0.12; Part Type: FET; PartType: FET; Power: 460MW; ROHS: Yes; Rated Power: 460MW; Rated Voltage: 20V
R45 = RES: Res 4M7 5% 1/16W -400/150PPM 50V 0402; ALT_SYMBOLS: RESC100X50X40RND; Agile Part Number: RES-00323-01; Barcode: 200358; CIP Link: http://xsjbrdwin1/CIP-E/Component/Index/All?pn=200358; OWNER: 10460; PRICE: 0; Part Type: SMT - 5%; PartType: SMT - 5%; Power: 1/10W; ROHS: Yes; Rated Power: 1/16W; Tolerance: 5%; primarykey: 207
R46-R49 R54 R58 R60 R61 R65 R75 R1784-R1786 = RES: Res 4K7 1% 1/16W 100PPM 50V 0402; ALT_SYMBOLS: RESC100X50X40RND; Agile Part Number: RES-00035-01; Barcode: 200067; CIP Link: http://xsjbrdwin1/CIP-E/Component/Index/All?pn=200067; OWNER: 3670; PRICE: 0.01; Part Type: SMT - 1%; PartType: SMT - 1%; Power: 1/16W; ROHS: Yes; Rated Power: 1/16W; Tolerance: 1%; primarykey: 128
R50-R53 R70 R71 = RES: Res 499R 1% 1/16W 100PPM 50V 0402; ALT_SYMBOLS: RESC100X50X40RND; Agile Part Number: RES-00028-01; Barcode: 200071; CIP Link: http://xsjbrdwin1/CIP-E/Component/Index/All?pn=200071; OWNER: 10460; PRICE: 0; Part Type: SMT - 1%; PartType: SMT - 1%; Power: 1/10W; ROHS: Yes; Rated Power: 1/16W; Tolerance: 1%; primarykey: 79
R55 R56 R59 R62-R64 = RES: Res 261R 1% 1/16W 100PPM 50V 0402; ALT_SYMBOLS: RESC100X50X40RND; Agile Part Number: RES-00086-01; Barcode: 200050; CIP Link: http://xsjbrdwin1/CIP-E/Component/Index/All?pn=200050; OWNER: 3501; PRICE: 0; Part Type: SMT - 1%; PartType: SMT - 1%; Power: 1/10W; ROHS: Yes; Rated Power: 1/16W; Tolerance: 1%; primarykey: 60
R57 = RES: Res 20R 1% 1/16W 100PPM 50V 0402; ALT_SYMBOLS: RESC100X50X40RND; Agile Part Number: RES-00033-01; Barcode: 200119; CIP Link: http://xsjbrdwin1/CIP-E/Component/Index/All?pn=200119; OWNER: 4001; PRICE: 0; Part Type: SMT - 1%; PartType: SMT - 1%; Power: 1/16W; ROHS: Yes; Rated Power: 1/16W; Tolerance: 1%; primarykey: 78
R66-R68 R72 = RES: Res 10K 1% 1/16W 100PPM 50V 0402; ALT_SYMBOLS: RESC100X50X40RND; Agile Part Number: RES-00030-01; Barcode: 200025; CIP Link: http://xsjbrdwin1/CIP-E/Component/Index/All?pn=200025; OWNER: 4001; PRICE: 0; Part Type: SMT - 1%; PartType: SMT - 1%; Power: 1/10W; ROHS: Yes; Rated Power: 1/16W; Tolerance: 1%; primarykey: 1
R69 = RES: Res 8K06 1% 1/16W 100PPM 50V 0402; ALT_SYMBOLS: RESC100X50X40RND; Agile Part Number: RES-00111-01; Barcode: 200083; CIP Link: http://xsjbrdwin1/CIP-E/Component/Index/All?pn=200083; OWNER: 3709; PRICE: 0; Part Type: SMT - 1%; PartType: SMT - 1%; Power: 1/10W; ROHS: Yes; Rated Power: 1/16W; Tolerance: 1%; primarykey: 74
SW2 = SW_DIP_4: Switch SPST-NO DIP 4 Pos 2.54mm P Ext 25mA 24V Black SMT; Agile Part Number: SWH-00011-01; Barcode: 440008; CIP Link: http://xsjbrdwin1/CIP-E/Component/Index/All?pn=440008; OWNER: 3709; PRICE: 0.8; Part Type: DIP; PartType: DIP; ROHS: Yes
SW3-SW5 = PUSHBUTTON-4: Switch SPST-NO Mom 50mA 50V 7.3mm H 100gf SMT; Agile Part Number: SWH-00014-01; Barcode: 440011; CIP Link: http://xsjbrdwin1/CIP-E/Component/Index/All?pn=440011; OWNER: 3709; PRICE: 0.25; Part Type: MOMENT; PartType: MOMENT; ROHS: Yes
U3 U4 = SN74AVC1T45: IC Lvl Trans 1-Bit 500Mbps 1.2-3.6V 12mA SC70-6; Agile Part Number: ICS-00084-01; Barcode: 500060; CIP Link: http://xsjbrdwin1/CIP-E/Component/Index/All?pn=500060; Family: BUS TRANSCEIVER; Part Type: BUS TRANSCEIVER; ROHS: Yes
U5 = MAX16025: IC  V. Sup 2-Ch 28Vin 2-Outs 1 Reset Out 20mA Iout TQFN-16; Agile Part Number: ICS-00075-01; Barcode: 500049; CIP Link: http://xsjbrdwin1/CIP-E/Component/Index/All?pn=500049; Family: VOLTAGE SUPERVISOR; Part Type: VOLTAGE SUPERVISOR; ROHS: Yes
X1 = XTAL_32KHZ_20PPM: Xtal 32.768KHz 1uW 70000R 12.5pF 20PPM 3215; Agile Part Number: XTL-00008-01; Barcode: 600083; CIP Link: http://xsjbrdwin1/CIP-E/Component/Index/All?pn=600083; Part Type: CRYSTAL
R73 = RES: Res 240R 1% 1/16W 100PPM 50V 0402; ALT_SYMBOLS: RESC100X50X40RND; Agile Part Number: RES-00018-01; Barcode: 200046; CIP Link: http://xsjbrdwin1/CIP-E/Component/Index/All?pn=200046; OWNER: 3670; PRICE: 0; Part Type: SMT - 1%; PartType: SMT - 1%; Power: 1/10W; ROHS: Yes; Rated Power: 1/16W; Tolerance: 1%; primarykey: 103
C11-C14 C19 C20 C36 C37 = CAP_NP: Cap Cer 10nF 10% 50V X7R 0402; ALT_SYMBOLS: CAPC100X50X55RND; Agile Part Number: CAP-00031-01; CIP Link: http://xsjbrdwin1/CIP-E/Component/Index/All?pn=100003; Dielectric Type: X7R; OWNER: 4001; PRICE: 0; Part Type: CERAMIC; PartType: CERAMIC; ROHS: Yes; Tolerance: 10%; Voltage: 50VDC; barcode: 100003
C38 = CAP_NP: Cap Cer 1uF 10% 35V X5R 0402; ALT_SYMBOLS: CAPC100X50X60RND; Agile Part Number: CAP-00165-01; CIP Link: http://xsjbrdwin1/CIP-E/Component/Index/All?pn=100192; Dielectric Type: X5R; OWNER: 3709; PRICE: 0.04; Part Type: CERAMIC; PartType: CERAMIC; ROHS: Yes; Tolerance: 10%; Voltage: 35V; barcode: 100192
C3084 C3085 C3098 C3099 = CAP_NP: Cap Cer 100nF 10% 25V X5R 0201; ALT_SYMBOLS: CAPC60X30X40RND; Agile Part Number: CAP-00142-01; Barcode: 100161; CIP Link: http://xsjbrdwin1/CIP-E/Component/Index/All?pn=100161; Dielectric Type: X5R; Part Type: CERAMIC; Tolerance: 10%; Voltage: 25V
R74 = RES: Res 499R 0.1% 1/16W 25PPM 50V 0402; Agile Part Number: RES-00594-01; Barcode: 20000072; CIP Link: http://xsjbrdwin1/CIP-E/Component/Index/All?pn=20000072; Part Type: SMT - 0.1%; Rated Power: 0.063W, 1/16W; Tolerance: 0.1%
R1763 R1764 = RES: Res 100R 1% 1/20W 200PPM 25V 0201; Agile Part Number: RES-00129-01; Barcode: 200116; CIP Link: http://xsjbrdwin1/CIP-E/Component/Index/All?pn=200116; Part Type: SMT - 1%; Rated Power: 1/20W; Tolerance: 1%
U429 = SI53340: IC BUFFER 2:4 LVDS MUX 16QFN; Agile Part Number: ICS-00217-01; Barcode: 500294; CIP Link: http://xsjbrdwin1/CIP-E/Component/Index/All?pn=500294; Part Type: CLOCK MULTIPLIER
B1 = BATTERY: Battery Coin Lithium 1.5V 2.5mAh 6.8mm D 6.8mm H TH Rechargeable; Agile Part Number: ICS-00485-01; Barcode: 740031; CIP Link: http://xsjbrdwin1/CIP-E/Component/Index/All?pn=740031; ROHS: Yes
C40 = CAP_NP: Cap Cer 10uF 20%  6.3V X6S 0402; ALT_SYMBOLS: CAPC100X50X55RND; Agile Part Number: CAP-00035-01; CIP Link: http://xsjbrdwin1/CIP-E/Component/Index/All?pn=100268; Dielectric Type: X6S; OWNER: 3670; PRICE: 0.04; Part Type: CERAMIC; PartType: CERAMIC; ROHS: Yes; Tolerance: 20%; Voltage: 6.3V; barcode: 100268
C41 C43 = CAP_NP: Cap Cer 470nF 10% 10V X5R 0402; ALT_SYMBOLS: CAPC100X50X55RND; Agile Part Number: CAP-00054-01; CIP Link: http://xsjbrdwin1/CIP-E/Component/Index/All?pn=100022; Dielectric Type: X5R; OWNER: 4001; PRICE: 0.02; Part Type: CERAMIC; PartType: CERAMIC; ROHS: Yes; Tolerance: 10%; Voltage: 10V; barcode: 100022
D3 = BAS40-04: Diode Schottky 200mA Iav 40V SOT-23 Dual; Agile Part Number: DIO-00007-01; Barcode: 300001; CIP Link: http://xsjbrdwin1/CIP-E/Component/Index/All?pn=300001; OWNER: 3709; PRICE: 0.17; Part Type: SWITCHING; PartType: SWITCHING; Power: 200MW; ROHS: 1; Rated Power: 200MW; Voltage: 40V
L3 = IND: Bead 120R 25% 3A 25mR 0603; Agile Part Number: IND-00017-01; Barcode: 300026; CIP Link: http://xsjbrdwin1/CIP-E/Component/Index/All?pn=300026; OWNER: 10460; PRICE: 0.04; Part Type: FERRITE; PartType: FERRITE; ROHS: Yes
L4 L5 = IND: Bead 600R 500mA 300mR 0805; Agile Part Number: FLT-00005-01; Barcode: 300009; CIP Link: http://xsjbrdwin1/CIP-E/Component/Index/All?pn=300009; OWNER: 4001; Part Type: FERRITE; PartType: FERRITE; ROHS: Yes
U1 = XCZU67DRFFVE1156_A
C44-C47 C1520 C1521 C1528 C1529 C1534 C1541 C1545-C1547 = CAP_NP: Cap Cer 100uF 20% 4V X6S 0805; ALT_SYMBOLS: CAPC200X125X145RND; Agile Part Number: CAP-00038-01; CIP Link: http://xsjbrdwin1/CIP-E/Component/Index/All?pn=100257; Dielectric Type: X6S; OWNER: 3709; PRICE: 0.35; Part Type: CERAMIC; PartType: CERAMIC; ROHS: Yes; Tolerance: 20%; Voltage: 4V; barcode: 100257
C48 C1525-C1527 C1531 C1532 C1538-C1540 C1542-C1544 C1548 C1553-C1555 C3043-C3046 = CAP_NP: Cap Cer 10uF 20%  6.3V X6S 0402; ALT_SYMBOLS: CAPC100X50X55RND; Agile Part Number: CAP-00035-01; CIP Link: http://xsjbrdwin1/CIP-E/Component/Index/All?pn=100268; Dielectric Type: X6S; OWNER: 3709; PRICE: 0.06; Part Type: CERAMIC; PartType: CERAMIC; ROHS: Yes; Tolerance: 20%; Voltage: 6.3V; barcode: 100268
C51 C52 = CAP_NP: Cap Cer 330uF 20% 2.5V X6S 1210; Agile Part Number: CAP-00190-01; Barcode: 100237; CIP Link: http://xsjbrdwin1/CIP-E/Component/Index/All?pn=100237; Dielectric Type: X6S; Equivalent Series Resistance: 0.7mohms; Part Type: CERAMIC; Tolerance: 20%; Voltage: 2.5V
C1522 C1524 C1530 C1535 C1537 = CAP_NP: Cap Cer 47uF 20% 2.5V X6S 0603; ALT_SYMBOLS: CAPC160X80X80RND; Agile Part Number: CAP-00010-01; CIP Link: http://xsjbrdwin1/CIP-E/Component/Index/All?pn=100255; Dielectric Type: X6S; OWNER: 3709; PRICE: 0.06; Part Type: CERAMIC; PartType: CERAMIC; ROHS: Yes; Tolerance: 20%; Voltage: 2.5V; barcode: 100255
C143 C157 = CAP_NP: Cap Cer 4.7uF 20% 6.3V X5R 0402; ALT_SYMBOLS: CAPC100X50X60RND; Agile Part Number: CAP-00085-01; CIP Link: http://xsjbrdwin1/CIP-E/Component/Index/All?pn=100067; Dielectric Type: X5R; OWNER: 3709; PRICE: 0.06; Part Type: CERAMIC; PartType: CERAMIC; ROHS: Yes; Tolerance: 20%; Voltage: 6.3V; barcode: 100067

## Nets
GND: B1.2(N) C25.2 C26.2 C27.2 C28.2 C29.2 C30.2 C31.2 C32.2 C33.2 C34.2 C35.2 C38.2 C40.2 C41.2 C44.2 C45.2 C46.2 C47.2 C48.2 C51.2 C52.2 C143.2 C157.2 C1520.2 C1521.2 C1522.2 C1524.2 C1525.2 C1526.2 C1527.2 C1528.2 C1529.2 C1530.2 C1531.2 C1532.2 C1534.2 C1535.2 C1537.2 C1538.2 C1539.2 C1540.2 C1541.2 C1542.2 C1543.2 C1544.2 C1545.2 C1546.2 C1547.2 C1548.2 C1553.2 C1554.2 C1555.2 C3043.2 C3044.2 C3045.2 C3046.2 DS2.2(GRN_CATHODE) DS3.1 J17.2(P2) L5.2 Q2.2(SOURCE) Q3.2(SOURCE) R50.2 R51.2 R52.2 R53.2 R70.2 R71.2 R72.2 R73.2 R74.2 SW3.3(P3) SW3.4(P4) SW4.3(P3) SW4.4(P4) SW5.3(P3) SW5.4(P4) U1.A1(DAC_GND) U1.A2(DAC_GND) U1.A3(DAC_GND) U1.A5(DAC_GND) U1.A7(DAC_GND) U1.A8(GND) U1.A11(GND) U1.A16(GND) U1.A21(GND) U1.A26(GND) U1.A27(GND) U1.A29(GND) U1.A30(GND) U1.A33(GND) U1.A34(GND) U1.AA1(ADC_GND) U1.AA2(ADC_GND) U1.AA3(ADC_GND) U1.AA4(ADC_GND) U1.AA5(ADC_GND) U1.AA6(ADC_GND) U1.AA8(ADC_GND) U1.AA9(GND) U1.AA11(GND) U1.AA13(GND) U1.AA15(GND) U1.AA17(GND) U1.AA19(GND) U1.AA21(GND) U1.AA25(GND) U1.AA28(GND) U1.AA29(GND) U1.AA30(GND) U1.AA33(GND) U1.AA34(GND) U1.AB3(ADC_GND) U1.AB6(ADC_GND) U1.AB8(ADC_GND) U1.AB10(GND) U1.AB12(GND) U1.AB14(GND) U1.AB16(GND) U1.AB19(GND) U1.AB21(GND) U1.AB22(GND) U1.AB30(GND) U1.AB32(GND) U1.AC1(ADC_GND) U1.AC2(ADC_GND) U1.AC3(ADC_GND) U1.AC4(ADC_GND) U1.AC5(ADC_GND) U1.AC6(ADC_GND) U1.AC8(ADC_SUB_GND) U1.AC9(GND) U1.AC11(GND) U1.AC18(GND) U1.AC19(GND) U1.AC21(GND) U1.AC26(GND) U1.AC31(GND) U1.AC32(GND) U1.AC33(GND) U1.AC34(GND) U1.AD3(ADC_GND) U1.AD6(ADC_GND) U1.AD8(ADC_GND) U1.AD10(GND) U1.AD12(GND) U1.AD14(GND) U1.AD20(GND) U1.AD22(GND) U1.AD24(GND) U1.AD29(GND) U1.AE1(ADC_GND) U1.AE2(ADC_GND) U1.AE3(ADC_GND) U1.AE4(ADC_GND) U1.AE5(ADC_GND) U1.AE6(ADC_GND) U1.AE8(ADC_GND) U1.AE9(GND) U1.AE17(GND) U1.AE19(GND) U1.AE21(GND) U1.AE27(GND) U1.AE32(GND) U1.AF3(ADC_GND) U1.AF6(ADC_GND) U1.AF8(ADC_GND) U1.AF9(GND) U1.AF20(GND) U1.AF22(GND) U1.AF30(GND) U1.AG1(ADC_GND) U1.AG2(ADC_GND) U1.AG3(ADC_GND) U1.AG6(ADC_GND) U1.AG8(GND) U1.AG13(GND) U1.AG18(GND) U1.AG23(GND) U1.AG33(GND) U1.AH3(ADC_GND) U1.AH6(ADC_GND) U1.AH8(GND) U1.AH16(GND) U1.AH21(GND) U1.AH26(GND) U1.AH31(GND) U1.AJ1(ADC_GND) U1.AJ2(ADC_GND) U1.AJ3(ADC_GND) U1.AJ6(ADC_GND) U1.AJ8(GND) U1.AJ19(GND) U1.AJ24(GND) U1.AJ29(GND) U1.AJ34(GND) U1.AK3(ADC_GND) U1.AK4(ADC_GND) U1.AK5(ADC_GND) U1.AK6(ADC_GND) U1.AK8(GND) U1.AK12(GND) U1.AK22(GND) U1.AK32(GND) U1.AL1(ADC_GND) U1.AL2(ADC_GND) U1.AL3(ADC_GND) U1.AL4(GND) U1.AL5(GND) U1.AL6(GND) U1.AL7(GND) U1.AL8(GND) U1.AL15(GND) U1.AL20(GND) U1.AL25(GND) U1.AM1(GND) U1.AM2(GND) U1.AM3(GND) U1.AM4(GND) U1.AM13(GND) U1.AM18(GND) U1.AM23(GND) U1.AM28(GND) U1.AM33(GND) U1.AN6(GND) U1.AN11(GND) U1.AN16(GND) U1.AN21(GND) U1.AN31(GND) U1.AP1(GND) U1.AP4(GND) U1.AP9(GND) U1.AP14(GND) U1.AP19(GND) U1.AP24(GND) U1.AP34(GND) U1.B1(DAC_GND) U1.B2(DAC_GND) U1.B3(DAC_GND) U1.B5(DAC_GND) U1.B7(DAC_GND) U1.B8(GND) U1.B9(GND) U1.B14(GND) U1.B19(GND) U1.B24(GND) U1.B27(GND) U1.B30(GND) U1.B31(GND) U1.B32(GND) U1.C3(DAC_GND) U1.C4(DAC_GND) U1.C5(DAC_GND) U1.C6(DAC_GND) U1.C7(DAC_GND) U1.C8(GND) U1.C12(GND) U1.C22(GND) U1.C27(GND) U1.C29(GND) U1.C32(GND) U1.C33(GND) U1.C34(GND) U1.D1(DAC_GND) U1.D2(DAC_GND) U1.D3(DAC_GND) U1.D5(DAC_GND) U1.D8(GND) U1.D15(GND) U1.D25(GND) U1.D27(GND) U1.D31(GND) U1.D32(GND) U1.E3(DAC_GND) U1.E5(DAC_GND) U1.E8(GND) U1.E18(GND) U1.E27(GND) U1.E29(GND) U1.E32(GND) U1.E33(GND) U1.E34(GND) U1.F1(DAC_GND) U1.F2(DAC_GND) U1.F3(DAC_GND) U1.F5(DAC_GND) U1.F7(DAC_GND) U1.F8(GND) U1.F11(GND) U1.F21(GND) U1.F26(GND) U1.F27(GND) U1.F31(GND) U1.F32(GND) U1.G3(DAC_GND) U1.G5(DAC_GND) U1.G8(GND) U1.G14(GND) U1.G24(GND) U1.G27(GND) U1.G32(GND) U1.G33(GND) U1.G34(GND) U1.H1(DAC_GND) U1.H2(DAC_GND) U1.H3(DAC_GND) U1.H4(DAC_GND) U1.H5(DAC_GND) U1.H6(DAC_GND) U1.H8(GND) U1.H17(GND) U1.H22(GND) U1.H27(GND) U1.H31(GND) U1.H32(GND) U1.J3(DAC_GND) U1.J6(DAC_GND) U1.J8(DAC_GND) U1.J9(GND) U1.J10(GND) U1.J15(GND) U1.J21(GND) U1.J23(GND) U1.J26(GND) U1.J27(GND) U1.J29(GND) U1.J32(GND) U1.J33(GND) U1.J34(GND) U1.K1(DAC_GND) U1.K2(DAC_GND) U1.K3(DAC_GND) U1.K4(DAC_GND) U1.K5(DAC_GND) U1.K6(DAC_GND) U1.K8(DAC_GND) U1.K13(GND) U1.K18(GND) U1.K21(GND) U1.K23(GND) U1.K27(GND) U1.K31(GND) U1.K32(GND) U1.L3(DAC_GND) U1.L6(DAC_GND) U1.L8(DAC_SUB_GND) U1.L9(GND) U1.L11(GND) U1.L13(GND) U1.L15(GND) U1.L17(GND) U1.L19(GND) U1.L21(GND) U1.L23(GND) U1.L25(GND) U1.L27(GND) U1.L29(GND) U1.L32(GND) U1.L33(GND) U1.L34(GND) U1.M1(DAC_GND) U1.M2(DAC_GND) U1.M3(DAC_GND) U1.M4(DAC_GND) U1.M5(DAC_GND) U1.M6(DAC_GND) U1.M8(DAC_GND) U1.M10(GND) U1.M12(GND) U1.M14(GND) U1.M16(GND) U1.M19(GND) U1.M21(GND) U1.M23(GND) U1.M27(GND) U1.M31(GND) U1.M32(GND) U1.N3(DAC_GND) U1.N6(DAC_GND) U1.N8(DAC_GND) U1.N9(GND) U1.N11(GND) U1.N13(GND) U1.N15(GND) U1.N17(GND) U1.N19(GND) U1.N21(GND) U1.N23(GND) U1.N27(GND) U1.N29(GND) U1.N32(GND) U1.N33(GND) U1.N34(GND) U1.P1(DAC_GND) U1.P2(DAC_GND) U1.P3(DAC_GND) U1.P4(DAC_GND) U1.P5(DAC_GND) U1.P6(DAC_GND) U1.P8(DAC_GND) U1.P10(GND) U1.P12(GND) U1.P14(GND) U1.P16(GND) U1.P19(GND) U1.P21(GND) U1.P23(GND) U1.P24(GND) U1.P27(GND) U1.P30(GND) U1.P31(GND) U1.P32(GND) U1.R1(ADC_GND) U1.R2(ADC_GND) U1.R3(ADC_GND) U1.R4(DAC_GND) U1.R5(DAC_GND) U1.R6(DAC_GND) U1.R7(DAC_GND) U1.R8(DAC_GND) U1.R9(GND) U1.R11(GND) U1.R13(GND) U1.R17(GND) U1.R19(GND) U1.R21(GND) U1.R23(GND) U1.R27(GND) U1.R29(GND) U1.R32(GND) U1.R33(GND) U1.R34(GND) U1.T3(ADC_GND) U1.T4(ADC_GND) U1.T5(ADC_GND) U1.T6(DAC_GND) U1.T7(DAC_GND) U1.T8(DAC_GND) U1.T10(GND) U1.T12(GND) U1.T16(GND) U1.T19(GND) U1.T21(GND) U1.T23(GND) U1.T27(GND) U1.T30(GND) U1.T32(GND) U1.U1(ADC_GND) U1.U2(ADC_GND) U1.U3(ADC_GND) U1.U4(ADC_GND) U1.U5(ADC_GND) U1.U6(ADC_GND) U1.U7(DAC_GND) U1.U8(DAC_GND) U1.U9(GND) U1.U11(GND) U1.U13(GND) U1.U17(GND) U1.U19(GND) U1.U21(GND) U1.U23(GND) U1.U27(GND) U1.U29(GND) U1.U30(GND) U1.U33(GND) U1.U34(GND) U1.V3(ADC_GND) U1.V6(ADC_GND) U1.V7(ADC_GND) U1.V8(ADC_GND) U1.V10(GND) U1.V12(GND) U1.V16(GND) U1.V19(GND) U1.V21(GND) U1.V23(GND) U1.V26(GND) U1.V27(GND) U1.V28(GND) U1.V32(GND) U1.W1(ADC_GND) U1.W2(ADC_GND) U1.W3(ADC_GND) U1.W4(ADC_GND) U1.W5(ADC_GND) U1.W6(ADC_GND) U1.W8(ADC_GND) U1.W9(GND) U1.W11(GND) U1.W13(GND) U1.W15(GND) U1.W17(GND) U1.W19(GND) U1.W21(GND) U1.W23(GND) U1.W24(GND) U1.W28(GND) U1.W30(GND) U1.W33(GND) U1.W34(GND) U1.Y3(ADC_GND) U1.Y6(ADC_GND) U1.Y8(ADC_GND) U1.Y10(GND) U1.Y12(GND) U1.Y14(GND) U1.Y16(GND) U1.Y18(GND) U1.Y19(GND) U1.Y21(GND) U1.Y22(GND) U1.Y28(GND) U1.Y32(GND) U3.2(GND) U3.5(DIR) U4.2(GND) U4.5(DIR) U5.4(TOL) U5.5(GND) U5.17(EPAD) U429.1(GND) U429.17(GNDPAD) ; also on sheet 3 4 5 7 8 9 20 21 22 23 24 25 26 27 28 32 33 34 35 36 37 38 39 40 41 42 43 44 45 46 47 48 49 50 51 52 53 54 55 56 57 58 59 60 61 62 63 64 65 66 67 68 69 70 71 72
VCC1V2: C1537.1 C1538.1 C1539.1 C1545.1 C3046.1 U1.AF25(VCCO_PSDDR_504) U1.AG28(VCCO_PSDDR_504) U1.AK27(VCCO_PSDDR_504) U1.AL30(VCCO_PSDDR_504) U1.AN26(VCCO_PSDDR_504) U1.AP29(VCCO_PSDDR_504) ; also on sheet 4 25 27 40 41 42 48 59 65 66 67 68
VCC1V8: C1530.1 C1531.1 C1532.1 C1534.1 C1535.1 C1542.1 C1543.1 C1544.1 C1547.1 C3043.1 C3044.1 C3045.1 D3.3 L3.2 L4.2 U1.AA10(VCCAUX_IO) U1.AC10(VCCAUX_IO) U1.L10(VCCAUX) U1.N10(VCCAUX) U1.N26(VCCO_PSIO3_503) U1.R10(VCCAUX) U1.T25(VCCO_PSIO3_503) U1.U10(VCCAUX_IO) U1.U24(VCC_PSAUX) U1.U25(VCC_PSAUX) U1.U26(VCC_PSAUX) U1.V25(VCC_PSAUX) U1.W10(VCCAUX_IO) ; also on sheet 3 5 9 52 69
VCC1V8_BUS: C28.1 C31.1 C38.1 R46.1 R47.1 R48.1 R49.1 R54.1 R58.1 R60.1 R61.1 R65.1 R69.1 R1784.1 R1785.1 R1786.1 U3.6(VCCB) U4.6(VCCB) U429.5(VDD) ; also on sheet 4 9 20 21 22 23 24 25 26 27 34 36 37 38 39 42 52 61 62 64
VCC_PSBATT: B1.1(P) R75.2 U1.V24(VCC_PSBATT)
VCC_PSDDR_PLL: C40.1 C41.1 L3.1 U1.Y24(VCC_PSDDR_PLL) U1.Y25(VCC_PSDDR_PLL)
VCCINT: C44.1 C45.1 C46.1 C47.1 C48.1 C51.1 C52.1 C1520.1 C1521.1 C1522.1 U1.AA12(VCCINT) U1.AA14(VCCINT) U1.AA16(VCCINT) U1.AA22(VCCINT) U1.AB11(VCCINT) U1.AB13(VCCINT) U1.AB15(VCCINT) U1.AC22(VCCINT) U1.AE22(VCCINT) U1.J22(VCCINT) U1.K22(VCCINT) U1.L12(VCCINT) U1.L14(VCCINT) U1.L16(VCCINT) U1.L18(VCCINT) U1.L22(VCCINT) U1.M11(VCCINT) U1.M13(VCCINT) U1.M15(VCCINT) U1.M17(VCCINT) U1.M18(VCCINT) U1.M22(VCCINT) U1.N12(VCCINT) U1.N14(VCCINT) U1.N16(VCCINT) U1.N18(VCCINT) U1.N22(VCCINT) U1.P11(VCCINT) U1.P13(VCCINT) U1.P15(VCCINT) U1.P17(VCCINT) U1.P18(VCCINT) U1.P22(VCCINT) U1.R12(VCCINT) U1.R16(VCCINT) U1.R18(VCCINT) U1.R22(VCCINT) U1.T11(VCCINT) U1.T13(VCCINT) U1.T17(VCCINT) U1.T18(VCCINT) U1.T22(VCCINT) U1.U12(VCCINT) U1.U16(VCCINT) U1.U18(VCCINT) U1.U22(VCCINT) U1.V11(VCCINT) U1.V13(VCCINT) U1.V17(VCCINT) U1.V18(VCCINT) U1.V22(VCCINT) U1.W12(VCCINT) U1.W14(VCCINT) U1.W16(VCCINT) U1.W18(VCCINT) U1.W22(VCCINT) U1.Y11(VCCINT) U1.Y13(VCCINT) U1.Y15(VCCINT) U1.Y17(VCCINT) ; also on sheet 3 44 45 69
VCCINT_AMS: U1.AB9(VCCINT_AMS) U1.AD9(VCCINT_AMS) U1.K9(VCCINT_AMS) U1.M9(VCCINT_AMS) U1.P9(VCCINT_AMS) U1.T9(VCCINT_AMS) U1.V9(VCCINT_AMS) U1.Y9(VCCINT_AMS) ; also on sheet 44 45 69
VCCINT_IO_BRAM_PS: C1524.1 C1525.1 C1526.1 C1527.1 C1528.1 C1529.1 C1540.1 C1541.1 U1.AA18(VCCBRAM) U1.AA23(VCC_PSINTFP) U1.AA24(VCC_PSINTLP) U1.AA26(VCC_PSINTLP) U1.AA27(VCC_PSINTLP) U1.AB17(VCCBRAM) U1.AB18(VCCBRAM) U1.AB23(VCC_PSINTFP) U1.AB24(VCC_PSINTFP) U1.AB25(VCC_PSINTLP) U1.AB26(VCC_PSINTLP) U1.AB27(VCC_PSINTLP) U1.AC23(VCC_PSINTFP) U1.AC24(VCC_PSINTFP) U1.AC25(VCC_PSINTFP_DDR) U1.AD19(VCCINT_IO) U1.AD23(VCC_PSINTFP) U1.AD25(VCC_PSINTFP_DDR) U1.AD26(VCC_PSINTFP_DDR) U1.AF19(VCCINT_IO) U1.Y23(VCC_PSINTFP) ; also on sheet 50 69
ADC_AVCC: U1.AA7(ADC_AVCC) U1.AB7(ADC_AVCC) U1.AC7(ADC_AVCC) U1.AD7(ADC_AVCC) U1.AE7(ADC_AVCC) U1.W7(ADC_AVCC) U1.Y7(ADC_AVCC) ; also on sheet 53 70
ADC_AVCCAUX: U1.AG7(ADC_AVCCAUX) U1.AH7(ADC_AVCCAUX) U1.AJ7(ADC_AVCCAUX) U1.AK7(ADC_AVCCAUX) ; also on sheet 54 70
BUF_GTR_REF_CLK0_N: C11.2 U429.10(Q0_B)
BUF_GTR_REF_CLK0_P: C12.2 U429.9(Q0)
BUF_GTR_REF_CLK1_N: C13.2 U429.12(Q1_B)
BUF_GTR_REF_CLK1_P: C14.2 U429.11(Q1)
BUF_GTR_REF_CLK3_N: C19.2 U429.14(Q2_B)
BUF_GTR_REF_CLK3_P: C20.2 U429.13(Q2)
DAC_AVCC: U1.G6(DAC_AVCC) U1.G7(DAC_AVCC) U1.H7(DAC_AVCC) U1.J7(DAC_AVCC) U1.K7(DAC_AVCC) U1.L7(DAC_AVCC) U1.M7(DAC_AVCC) U1.N7(DAC_AVCC) U1.P7(DAC_AVCC) ; also on sheet 53 70
DAC_AVCCAUX: U1.D6(DAC_AVCCAUX) U1.D7(DAC_AVCCAUX) U1.E6(DAC_AVCCAUX) U1.E7(DAC_AVCCAUX) ; also on sheet 55 70
DAC_AVTT: U1.D4(DAC_AVTT) U1.E4(DAC_AVTT) U1.F4(DAC_AVTT) U1.G4(DAC_AVTT) ; also on sheet 55 70
FMCP_HSPC_DP4_C2M_N: U1.AA32(PS_MGTRTXN0_505) ; also on sheet 28
FMCP_HSPC_DP4_C2M_P: U1.AA31(PS_MGTRTXP0_505) ; also on sheet 28
FMCP_HSPC_DP4_M2C_N: U1.AB34(PS_MGTRRXN0_505) ; also on sheet 28
FMCP_HSPC_DP4_M2C_P: U1.AB33(PS_MGTRRXP0_505) ; also on sheet 28
FMCP_HSPC_DP5_C2M_N: U1.W32(PS_MGTRTXN1_505) ; also on sheet 28
FMCP_HSPC_DP5_C2M_P: U1.W31(PS_MGTRTXP1_505) ; also on sheet 28
FMCP_HSPC_DP5_M2C_N: U1.Y34(PS_MGTRRXN1_505) ; also on sheet 28
FMCP_HSPC_DP5_M2C_P: U1.Y33(PS_MGTRRXP1_505) ; also on sheet 28
FMCP_HSPC_DP6_C2M_N: U1.R31(PS_MGTRTXN3_505) ; also on sheet 28
FMCP_HSPC_DP6_C2M_P: U1.R30(PS_MGTRTXP3_505) ; also on sheet 28
FMCP_HSPC_DP6_M2C_N: U1.T34(PS_MGTRRXN3_505) ; also on sheet 28
FMCP_HSPC_DP6_M2C_P: U1.T33(PS_MGTRRXP3_505) ; also on sheet 28
FMCP_HSPC_GBTCLK1_M2C_C_N: C3085.2 R1764.1 U429.4(CLK1_B)
FMCP_HSPC_GBTCLK1_M2C_C_P: C3084.2 R1764.2 U429.3(CLK1)
FMCP_HSPC_GBTCLK1_M2C_N: C3085.1 ; also on sheet 28
FMCP_HSPC_GBTCLK1_M2C_P: C3084.1 ; also on sheet 28
FPGA_TCK: R57.1 R1784.2 U1.P26(PS_JTAG_TCK) ; also on sheet 25
FPGA_TDI: R1786.2 U1.M26(PS_JTAG_TDI) ; also on sheet 25
FPGA_TDO_FMC_TDI: U1.T26(PS_JTAG_TDO) ; also on sheet 25
FPGA_TMS: R1785.2 U1.N25(PS_JTAG_TMS) ; also on sheet 25
GT2_USB0_RX_N: U1.V34(PS_MGTRRXN2_505) ; also on sheet 20
GT2_USB0_RX_P: U1.V33(PS_MGTRRXP2_505) ; also on sheet 20
GT2_USB0_TX_N: U1.U32(PS_MGTRTXN2_505) ; also on sheet 20
GT2_USB0_TX_P: U1.U31(PS_MGTRTXP2_505) ; also on sheet 20
GTR_REF_CLK0_C_N: C11.1 U1.Y30(PS_MGTREFCLK0N_505)
GTR_REF_CLK0_C_P: C12.1 U1.Y29(PS_MGTREFCLK0P_505)
GTR_REF_CLK1_C_N: C13.1 U1.V30(PS_MGTREFCLK1N_505)
GTR_REF_CLK1_C_P: C14.1 U1.V29(PS_MGTREFCLK1P_505)
GTR_REF_CLK2_C_N: C19.1 U1.P29(PS_MGTREFCLK3N_505)
GTR_REF_CLK2_C_P: C20.1 U1.P28(PS_MGTREFCLK3P_505)
GTR_REF_CLK_USB3_C_N: C36.1 U1.T29(PS_MGTREFCLK2N_505)
GTR_REF_CLK_USB3_C_P: C37.1 U1.T28(PS_MGTREFCLK2P_505)
MGT1V2: C157.1 C1546.1 C1548.1 U1.D30(MGTAVTT) U1.F30(MGTAVTT) U1.H30(MGTAVTT) U1.K30(MGTAVTT) U1.M30(MGTAVTT) U1.W27(VCC_PSPLL) U1.Y26(VCC_PSPLL) U1.Y27(VCC_PSPLL) ; also on sheet 6 49 69
MGT1V8: C1554.1 C1555.1 U1.AB31(PS_MGTRAVTT) U1.J28(MGTVCCAUX) U1.L28(MGTVCCAUX) U1.V31(PS_MGTRAVTT) U1.Y31(PS_MGTRAVTT) ; also on sheet 47 69
MGTAVCC: C143.1 U1.A28(MGTAVCC) U1.C28(MGTAVCC) U1.E28(MGTAVCC) U1.N28(MGTAVCC) ; also on sheet 51 69
MGTRAVCC: C1553.1 U1.R28(PS_MGTRAVCC) U1.U28(PS_MGTRAVCC) U1.W29(PS_MGTRAVCC) ; also on sheet 49 69
PS_DDR4_SODIMM_A0: U1.AN29(PS_DDR_A0) ; also on sheet 40
PS_DDR4_SODIMM_A1: U1.AP27(PS_DDR_A1) ; also on sheet 40
PS_DDR4_SODIMM_A2: U1.AP25(PS_DDR_A2) ; also on sheet 40
PS_DDR4_SODIMM_A3: U1.AP26(PS_DDR_A3) ; also on sheet 40
PS_DDR4_SODIMM_A4: U1.AN27(PS_DDR_A4) ; also on sheet 40
PS_DDR4_SODIMM_A5: U1.AN25(PS_DDR_A5) ; also on sheet 40
PS_DDR4_SODIMM_A6: U1.AK26(PS_DDR_A6) ; also on sheet 40
PS_DDR4_SODIMM_A7: U1.AK25(PS_DDR_A7) ; also on sheet 40
PS_DDR4_SODIMM_A8: U1.AJ26(PS_DDR_A8) ; also on sheet 40
PS_DDR4_SODIMM_A9: U1.AJ25(PS_DDR_A9) ; also on sheet 40
PS_DDR4_SODIMM_A10: U1.AL28(PS_DDR_A10) ; also on sheet 40
PS_DDR4_SODIMM_A11: U1.AM26(PS_DDR_A11) ; also on sheet 40
PS_DDR4_SODIMM_A12: U1.AL29(PS_DDR_A12) ; also on sheet 40
PS_DDR4_SODIMM_A13: U1.AM25(PS_DDR_A13) ; also on sheet 40
PS_DDR4_SODIMM_ACT_B: U1.AH27(PS_DDR_ACT_N) ; also on sheet 40
PS_DDR4_SODIMM_ALERT_B: U1.AE26(PS_DDR_ALERT_N) ; also on sheet 40
PS_DDR4_SODIMM_BA0: U1.AG26(PS_DDR_BA0) ; also on sheet 40
PS_DDR4_SODIMM_BA1: U1.AK28(PS_DDR_BA1) ; also on sheet 40
PS_DDR4_SODIMM_BG0: U1.AJ27(PS_DDR_BG0) ; also on sheet 40
PS_DDR4_SODIMM_BG1: U1.AJ28(PS_DDR_BG1) ; also on sheet 40
PS_DDR4_SODIMM_CAS_B: U1.AL26(PS_DDR_A15) ; also on sheet 40
PS_DDR4_SODIMM_CK0_C: U1.AP28(PS_DDR_CK_N0) ; also on sheet 40
PS_DDR4_SODIMM_CK0_T: U1.AN28(PS_DDR_CK0) ; also on sheet 40
PS_DDR4_SODIMM_CK1_C: U1.AM27(PS_DDR_CK_N1) ; also on sheet 40
PS_DDR4_SODIMM_CK1_T: U1.AL27(PS_DDR_CK1) ; also on sheet 40
PS_DDR4_SODIMM_CKE0: U1.AP31(PS_DDR_CKE0) ; also on sheet 40
PS_DDR4_SODIMM_CKE1: U1.AK29(PS_DDR_CKE1) ; also on sheet 40
PS_DDR4_SODIMM_CS0_B: U1.AN30(PS_DDR_CS_N0) ; also on sheet 40
PS_DDR4_SODIMM_CS1_B: U1.AM30(PS_DDR_CS_N1) ; also on sheet 40
PS_DDR4_SODIMM_DM0_B: U1.AM20(PS_DDR_DM0) ; also on sheet 40
PS_DDR4_SODIMM_DM1_B: U1.AL23(PS_DDR_DM1) ; also on sheet 40
PS_DDR4_SODIMM_DM2_B: U1.AH20(PS_DDR_DM2) ; also on sheet 40
PS_DDR4_SODIMM_DM3_B: U1.AG22(PS_DDR_DM3) ; also on sheet 40
PS_DDR4_SODIMM_DM4_B: U1.AG31(PS_DDR_DM4) ; also on sheet 40
PS_DDR4_SODIMM_DM5_B: U1.AD31(PS_DDR_DM5) ; also on sheet 40
PS_DDR4_SODIMM_DM6_B: U1.AJ31(PS_DDR_DM6) ; also on sheet 40
PS_DDR4_SODIMM_DM7_B: U1.AE33(PS_DDR_DM7) ; also on sheet 40
PS_DDR4_SODIMM_DQ0: U1.AP22(PS_DDR_DQ0) ; also on sheet 40
PS_DDR4_SODIMM_DQ1: U1.AM21(PS_DDR_DQ1) ; also on sheet 40
PS_DDR4_SODIMM_DQ2: U1.AP21(PS_DDR_DQ2) ; also on sheet 40
PS_DDR4_SODIMM_DQ3: U1.AL21(PS_DDR_DQ3) ; also on sheet 40
PS_DDR4_SODIMM_DQ4: U1.AP18(PS_DDR_DQ4) ; also on sheet 40
PS_DDR4_SODIMM_DQ5: U1.AN19(PS_DDR_DQ5) ; also on sheet 40
PS_DDR4_SODIMM_DQ6: U1.AM19(PS_DDR_DQ6) ; also on sheet 40
PS_DDR4_SODIMM_DQ7: U1.AL19(PS_DDR_DQ7) ; also on sheet 40
PS_DDR4_SODIMM_DQ8: U1.AL22(PS_DDR_DQ8) ; also on sheet 40
PS_DDR4_SODIMM_DQ9: U1.AK23(PS_DDR_DQ9) ; also on sheet 40
PS_DDR4_SODIMM_DQ10: U1.AM22(PS_DDR_DQ10) ; also on sheet 40
PS_DDR4_SODIMM_DQ11: U1.AN22(PS_DDR_DQ11) ; also on sheet 40
PS_DDR4_SODIMM_DQ12: U1.AK24(PS_DDR_DQ12) ; also on sheet 40
PS_DDR4_SODIMM_DQ13: U1.AL24(PS_DDR_DQ13) ; also on sheet 40
PS_DDR4_SODIMM_DQ14: U1.AN24(PS_DDR_DQ14) ; also on sheet 40
PS_DDR4_SODIMM_DQ15: U1.AM24(PS_DDR_DQ15) ; also on sheet 40
PS_DDR4_SODIMM_DQ16: U1.AJ22(PS_DDR_DQ16) ; also on sheet 40
PS_DDR4_SODIMM_DQ17: U1.AK21(PS_DDR_DQ17) ; also on sheet 40
PS_DDR4_SODIMM_DQ18: U1.AK20(PS_DDR_DQ18) ; also on sheet 40
PS_DDR4_SODIMM_DQ19: U1.AK19(PS_DDR_DQ19) ; also on sheet 40
PS_DDR4_SODIMM_DQ20: U1.AG21(PS_DDR_DQ20) ; also on sheet 40
PS_DDR4_SODIMM_DQ21: U1.AG19(PS_DDR_DQ21) ; also on sheet 40
PS_DDR4_SODIMM_DQ22: U1.AG20(PS_DDR_DQ22) ; also on sheet 40
PS_DDR4_SODIMM_DQ23: U1.AH19(PS_DDR_DQ23) ; also on sheet 40
PS_DDR4_SODIMM_DQ24: U1.AE23(PS_DDR_DQ24) ; also on sheet 40
PS_DDR4_SODIMM_DQ25: U1.AF23(PS_DDR_DQ25) ; also on sheet 40
PS_DDR4_SODIMM_DQ26: U1.AE25(PS_DDR_DQ26) ; also on sheet 40
PS_DDR4_SODIMM_DQ27: U1.AE24(PS_DDR_DQ27) ; also on sheet 40
PS_DDR4_SODIMM_DQ28: U1.AH23(PS_DDR_DQ28) ; also on sheet 40
PS_DDR4_SODIMM_DQ29: U1.AH22(PS_DDR_DQ29) ; also on sheet 40
PS_DDR4_SODIMM_DQ30: U1.AJ23(PS_DDR_DQ30) ; also on sheet 40
PS_DDR4_SODIMM_DQ31: U1.AH24(PS_DDR_DQ31) ; also on sheet 40
PS_DDR4_SODIMM_DQ32: U1.AE29(PS_DDR_DQ32) ; also on sheet 40
PS_DDR4_SODIMM_DQ33: U1.AF29(PS_DDR_DQ33) ; also on sheet 40
PS_DDR4_SODIMM_DQ34: U1.AE28(PS_DDR_DQ34) ; also on sheet 40
PS_DDR4_SODIMM_DQ35: U1.AF28(PS_DDR_DQ35) ; also on sheet 40
PS_DDR4_SODIMM_DQ36: U1.AJ30(PS_DDR_DQ36) ; also on sheet 40
PS_DDR4_SODIMM_DQ37: U1.AH29(PS_DDR_DQ37) ; also on sheet 40
PS_DDR4_SODIMM_DQ38: U1.AH30(PS_DDR_DQ38) ; also on sheet 40
PS_DDR4_SODIMM_DQ39: U1.AH28(PS_DDR_DQ39) ; also on sheet 40
PS_DDR4_SODIMM_DQ40: U1.AE30(PS_DDR_DQ40) ; also on sheet 40
PS_DDR4_SODIMM_DQ41: U1.AD30(PS_DDR_DQ41) ; also on sheet 40
PS_DDR4_SODIMM_DQ42: U1.AD28(PS_DDR_DQ42) ; also on sheet 40
PS_DDR4_SODIMM_DQ43: U1.AD27(PS_DDR_DQ43) ; also on sheet 40
PS_DDR4_SODIMM_DQ44: U1.AB29(PS_DDR_DQ44) ; also on sheet 40
PS_DDR4_SODIMM_DQ45: U1.AC28(PS_DDR_DQ45) ; also on sheet 40
PS_DDR4_SODIMM_DQ46: U1.AB28(PS_DDR_DQ46) ; also on sheet 40
PS_DDR4_SODIMM_DQ47: U1.AC27(PS_DDR_DQ47) ; also on sheet 40
PS_DDR4_SODIMM_DQ48: U1.AG34(PS_DDR_DQ48) ; also on sheet 40
PS_DDR4_SODIMM_DQ49: U1.AH33(PS_DDR_DQ49) ; also on sheet 40
PS_DDR4_SODIMM_DQ50: U1.AH34(PS_DDR_DQ50) ; also on sheet 40
PS_DDR4_SODIMM_DQ51: U1.AH32(PS_DDR_DQ51) ; also on sheet 40
PS_DDR4_SODIMM_DQ52: U1.AK34(PS_DDR_DQ52) ; also on sheet 40
PS_DDR4_SODIMM_DQ53: U1.AK33(PS_DDR_DQ53) ; also on sheet 40
PS_DDR4_SODIMM_DQ54: U1.AK31(PS_DDR_DQ54) ; also on sheet 40
PS_DDR4_SODIMM_DQ55: U1.AK30(PS_DDR_DQ55) ; also on sheet 40
PS_DDR4_SODIMM_DQ56: U1.AG32(PS_DDR_DQ56) ; also on sheet 40
PS_DDR4_SODIMM_DQ57: U1.AF31(PS_DDR_DQ57) ; also on sheet 40
PS_DDR4_SODIMM_DQ58: U1.AF34(PS_DDR_DQ58) ; also on sheet 40
PS_DDR4_SODIMM_DQ59: U1.AE34(PS_DDR_DQ59) ; also on sheet 40
PS_DDR4_SODIMM_DQ60: U1.AD32(PS_DDR_DQ60) ; also on sheet 40
PS_DDR4_SODIMM_DQ61: U1.AE31(PS_DDR_DQ61) ; also on sheet 40
PS_DDR4_SODIMM_DQ62: U1.AD34(PS_DDR_DQ62) ; also on sheet 40
PS_DDR4_SODIMM_DQ63: U1.AD33(PS_DDR_DQ63) ; also on sheet 40
PS_DDR4_SODIMM_DQS0_C: U1.AP20(PS_DDR_DQS_N0) ; also on sheet 40
PS_DDR4_SODIMM_DQS0_T: U1.AN20(PS_DDR_DQS_P0) ; also on sheet 40
PS_DDR4_SODIMM_DQS1_C: U1.AP23(PS_DDR_DQS_N1) ; also on sheet 40
PS_DDR4_SODIMM_DQS1_T: U1.AN23(PS_DDR_DQS_P1) ; also on sheet 40
PS_DDR4_SODIMM_DQS2_C: U1.AJ21(PS_DDR_DQS_N2) ; also on sheet 40
PS_DDR4_SODIMM_DQS2_T: U1.AJ20(PS_DDR_DQS_P2) ; also on sheet 40
PS_DDR4_SODIMM_DQS3_C: U1.AG24(PS_DDR_DQS_N3) ; also on sheet 40
PS_DDR4_SODIMM_DQS3_T: U1.AF24(PS_DDR_DQS_P3) ; also on sheet 40
PS_DDR4_SODIMM_DQS4_C: U1.AG30(PS_DDR_DQS_N4) ; also on sheet 40
PS_DDR4_SODIMM_DQS4_T: U1.AG29(PS_DDR_DQS_P4) ; also on sheet 40
PS_DDR4_SODIMM_DQS5_C: U1.AC30(PS_DDR_DQS_N5) ; also on sheet 40
PS_DDR4_SODIMM_DQS5_T: U1.AC29(PS_DDR_DQS_P5) ; also on sheet 40
PS_DDR4_SODIMM_DQS6_C: U1.AJ33(PS_DDR_DQS_N6) ; also on sheet 40
PS_DDR4_SODIMM_DQS6_T: U1.AJ32(PS_DDR_DQS_P6) ; also on sheet 40
PS_DDR4_SODIMM_DQS7_C: U1.AF33(PS_DDR_DQS_N7) ; also on sheet 40
PS_DDR4_SODIMM_DQS7_T: U1.AF32(PS_DDR_DQS_P7) ; also on sheet 40
PS_DDR4_SODIMM_ODT0: U1.AP30(PS_DDR_ODT0) ; also on sheet 40
PS_DDR4_SODIMM_ODT1: U1.AM31(PS_DDR_ODT1) ; also on sheet 40
PS_DDR4_SODIMM_PARITY: U1.AG27(PS_DDR_PARITY) ; also on sheet 40
PS_DDR4_SODIMM_RAS_B: U1.AH25(PS_DDR_A16) ; also on sheet 40
PS_DDR4_SODIMM_WE_B: U1.AM29(PS_DDR_A14) ; also on sheet 40
PS_DONE: R58.2 U1.T24(PS_DONE) U4.4(B)
PS_ERR_OUT: Q2.1(GATE) R70.1 U1.J24(PS_ERROR_OUT)
PS_ERR_STATUS: Q3.1(GATE) R71.1 U1.R26(PS_ERROR_STATUS)
PS_INIT_B: R54.2 U1.R24(PS_INIT_B) U3.4(B)
PS_MODE0: J14.1(P1) R46.2 SW2.1 U1.L26(PS_MODE0)
PS_MODE1: J14.2(P2) R47.2 SW2.2 U1.L24(PS_MODE1) ; also on sheet 20
PS_MODE2: J14.3(P3) R48.2 SW2.3 U1.K24(PS_MODE2)
PS_MODE3: J14.4(P4) R49.2 SW2.4 U1.M24(PS_MODE3)
PS_PADI: C25.1 R45.1 U1.K26(PS_PADI) X1.1(X1)
PS_PADO: C26.1 R45.2 U1.K25(PS_PADO) X1.2(X2)
PS_POR_B: J15.1(P1) R60.2 U1.N24(PS_POR_B) ; also on sheet 20 24 25 26
PS_PROG_B: R65.2 SW3.1(P1) SW3.2(P2) U1.P25(PS_PROG_B)
PS_REF_CLK: U1.M25(PS_REF_CLK) ; also on sheet 42
PS_SRST_B: J16.1(P1) R61.2 U1.R25(PS_SRST_B) ; also on sheet 25
PS_SYSMON_AGND: C42.2 C43.2 L5.1 U1.W26(GND_PSADC)
PS_SYSMON_AVCC: C42.1 C43.1 L4.1 U1.W25(VCC_PSADC)
SI5381_GTR_REF_CLK_C_N: C3099.2 R1763.1 U429.7(CLK0_B)
SI5381_GTR_REF_CLK_C_P: C3098.2 R1763.2 U429.6(CLK0)
SI5381_GTR_REF_CLK_N: C3099.1 ; also on sheet 36
SI5381_GTR_REF_CLK_P: C3098.1 ; also on sheet 36
SI5381_GTR_REFCLK_USB3_N: C36.2 ; also on sheet 36
SI5381_GTR_REFCLK_USB3_P: C37.2 ; also on sheet 36
SI53340_MUX_GTR_SEL: U429.2(CLK_SEL) ; also on sheet 5
UTIL_3V3: C27.1 C30.1 C32.1 DS2.3(RED_ANODE) R62.1 R63.1 R64.1 R66.1 R67.1 R68.1 U3.1(VCCA) U4.1(VCCA) U5.1(VCC) ; also on sheet 9 20 22 23 24 25 26 27 28 29 30 31 33 34 36 37 40 42 43 44 45 47 49 51 53 54 55 56 57 59 60 61 64
ZYNQ_DDR4_SODIMM_RESET_B: U1.AF27(PS_DDR_RAM_RST_N) ; also on sheet 40
N16976600: C29.1 R57.2
N16976723: R50.1 SW2.5
N16976728: R51.1 SW2.6
N16976733: R52.1 SW2.7
N16976741: R53.1 SW2.8
N16996493: R59.1 U4.3(A)
N16996513: DS3.2 R59.2
N16996930: R55.1 R56.1 U3.3(A)
N16997258: DS2.4(RED_CATHODE) R55.2
N16997310: DS2.1(GRN_ANODE) R56.2
N16998848: C33.1 U5.14(CRESET)
N16998853: C34.1 U5.15(CDLY2)
N16998858: C35.1 U5.16(CDLY1)
N16998863: DS4.1 U5.12(RESET_B)
N16998914: DS4.2 R62.2
N16998948: J15.2(P2) U5.11(OUT1)
N16998951: J16.2(P2) U5.10(OUT2)
N17000320: D2.2(ANODE) R66.2 SW4.1(P1) SW4.2(P2) U5.6(EN1)
N17000323: D1.2(ANODE) R67.2 SW5.1(P1) SW5.2(P2) U5.7(EN2)
N17001032: D1.1(CATHODE) D2.1(CATHODE) J17.1(P1) R68.2 U5.13(MR_B)
N17001817: R69.2 R72.1 U5.2(IN1) U5.3(IN2)
N17004899: DS6.2 R64.2
N17004954: DS5.2 R63.2
N17005024: DS5.1 Q2.3(DRAIN)
N17005027: DS6.1 Q3.3(DRAIN)
N17010067: R73.1 U1.AF26(PS_DDR_ZQ)
N17536638: R74.1 U1.T31(PS_MGTRREF_505)
N18943690: D3.2 R75.1

Not connected (* = marked no-connect by the designer): D3 1*; U1 AA20(NC) AB20(NC) AC20(NC) AD21(NC) AE20(NC) AF21(NC) AG25(PS_DDR_A17) AL31(PS_DDR_DQ66) AL32(PS_DDR_DQ67) AL33(PS_DDR_DM8) AL34(PS_DDR_DQ71) AM32(PS_DDR_DQ65) AM34(PS_DDR_DQ69) AN32(PS_DDR_DQS_P8) AN33(PS_DDR_DQS_N8) AN34(PS_DDR_DQ70) AP32(PS_DDR_DQ64) AP33(PS_DDR_DQ68) G26(NC) H24(NC) H25(NC) H26(NC) J25(NC) M20(NC) N20(NC) P20(NC) R20(NC) T20(NC) U20(NC) V20(NC) W20(NC) Y20(NC); U5 8(TH1)* 9(TH0)*; U429 8(NC)* 15(Q3)* 16(Q3_B)*

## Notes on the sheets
sheet 12
- <== CLK MUX
- <== CLK MUX
- <== Si5381 USB CLK
- To be updated to GTR_REF_CLK3_C_P/N
- <== CLK MUX
- Default 0:CLK0
- GTR REFCLK MUX
sheet 16
- ZU47DR device: SDFEC power pins
sheet 17
- VCCINT
- UG583 (V1.19)
  ZU47DR FFVE1156 Guidelines
- VCCBRAM/VCCPSINTLP/VCCPSINTFP/VCCINT_IO
- No SDFEC
- VCCAUX/VCCPSAUX/VCCAUX_IO
- HD HP VCCO/VCCO_PSDDR
- VCC_PSIO
- VCC_PSPLL
sheet 18
- MGTAVCC
- MGTAVTT/VCCPSPLL
- MGTRAVCC
- MGTVCCAUX/MGTRAVTT
- AMS Scheme from UG583 1.15
  GTY scheme from UG567 1.3
  GTR scheme from Si Apps 5/10/19
